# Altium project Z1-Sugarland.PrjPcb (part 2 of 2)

## Sheet Z1-Sugarland-Simplified.SchDoc
size 1219 x 914 mm
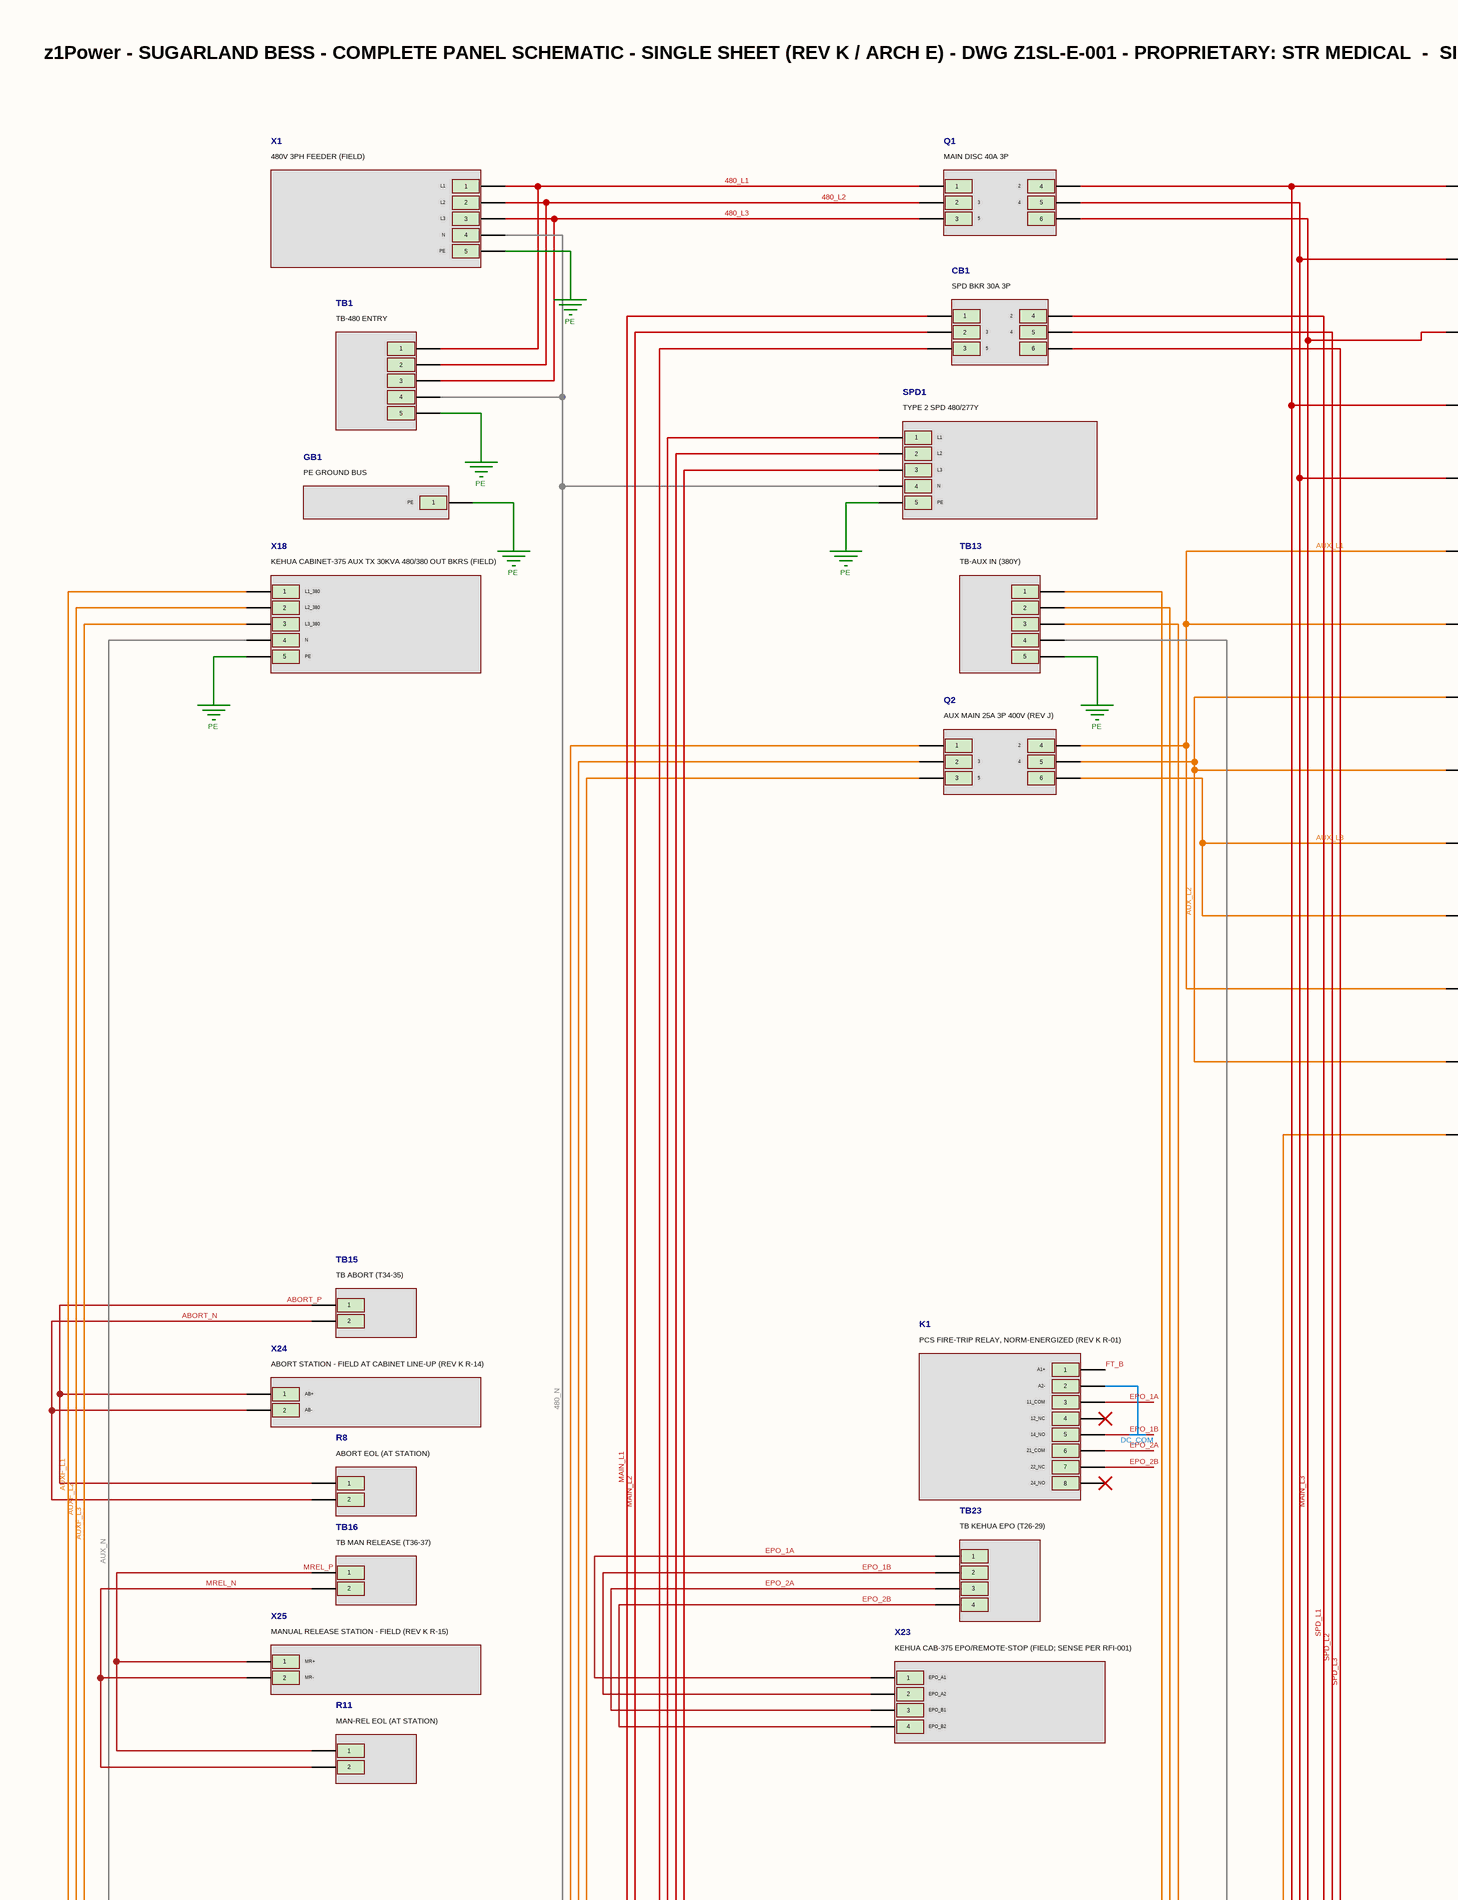
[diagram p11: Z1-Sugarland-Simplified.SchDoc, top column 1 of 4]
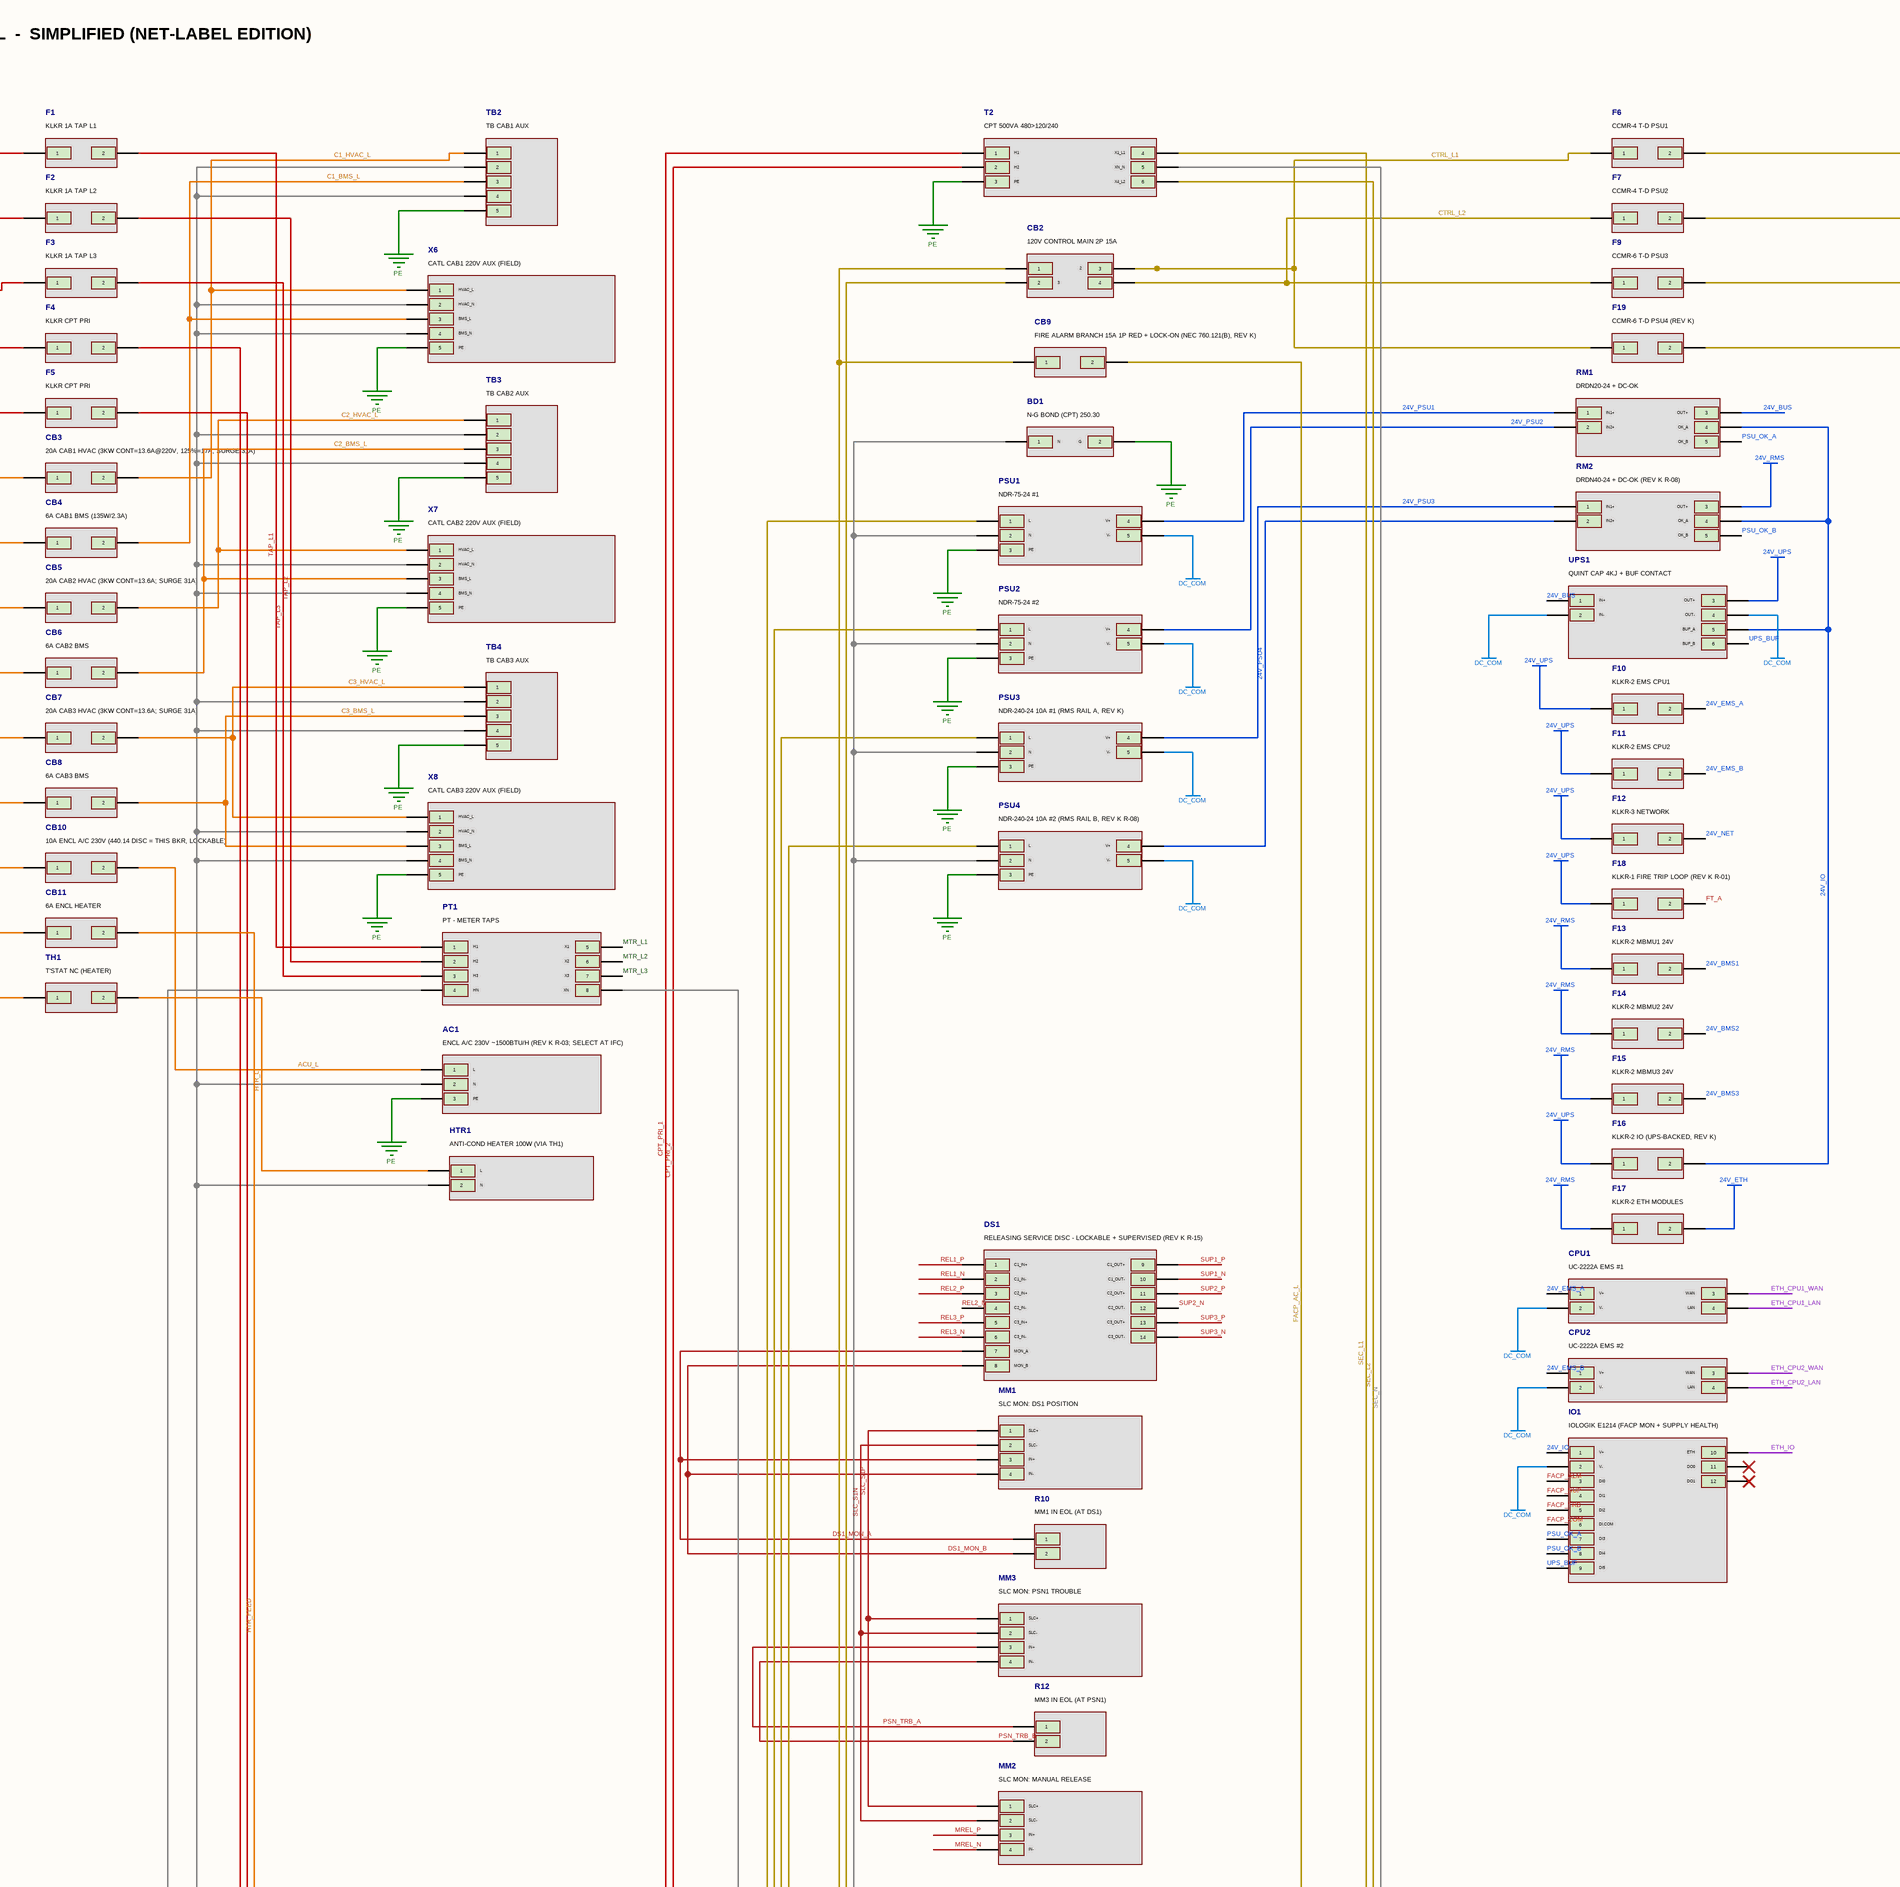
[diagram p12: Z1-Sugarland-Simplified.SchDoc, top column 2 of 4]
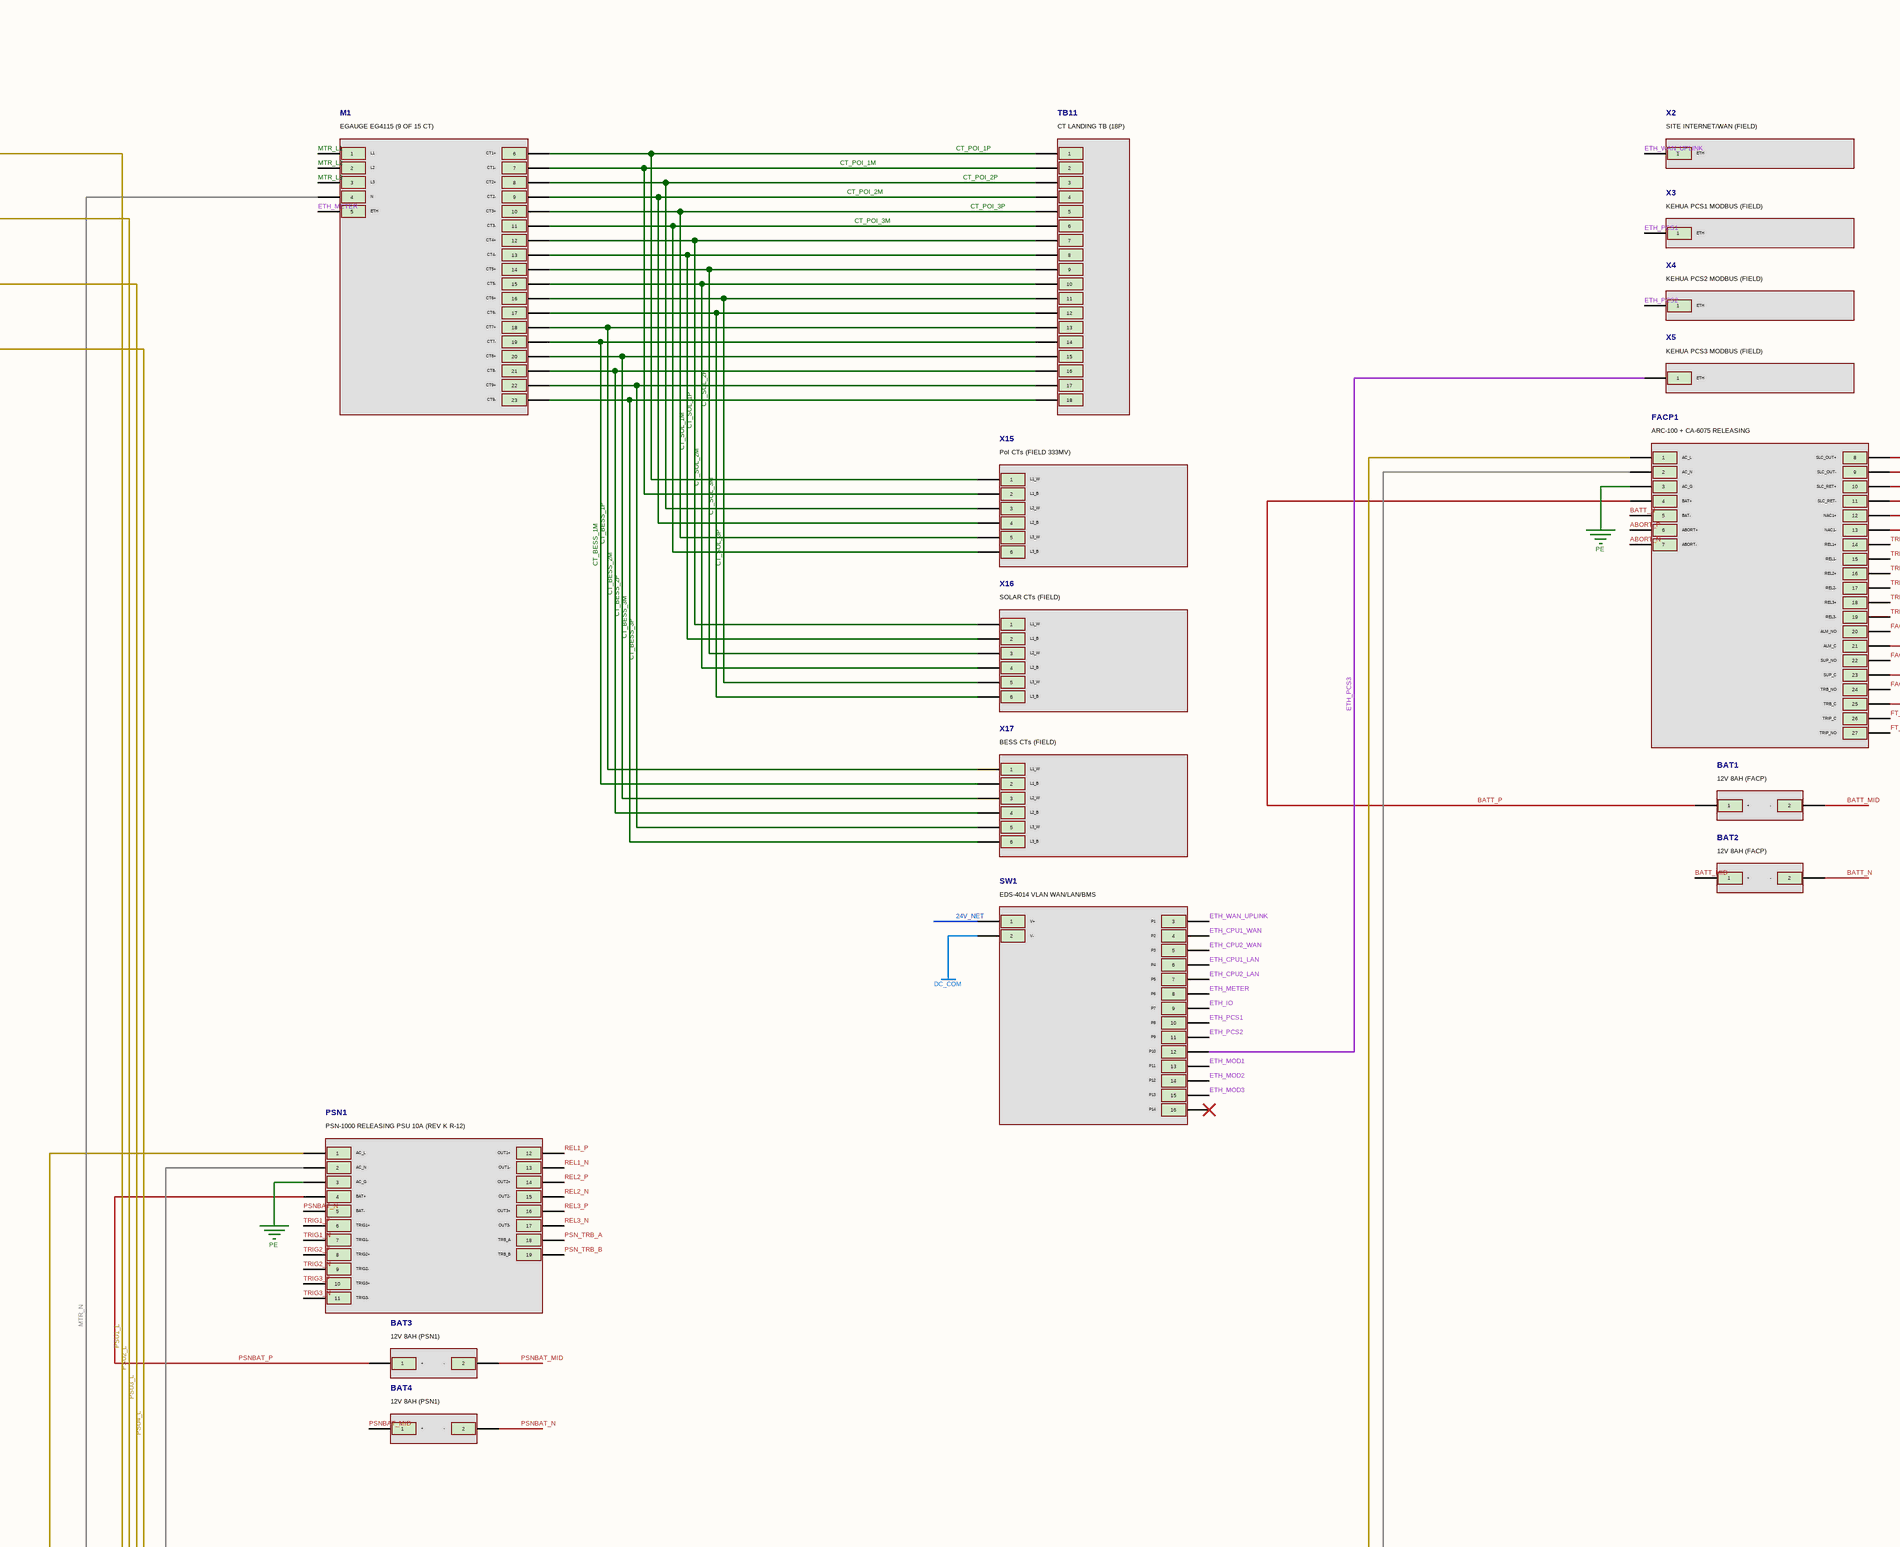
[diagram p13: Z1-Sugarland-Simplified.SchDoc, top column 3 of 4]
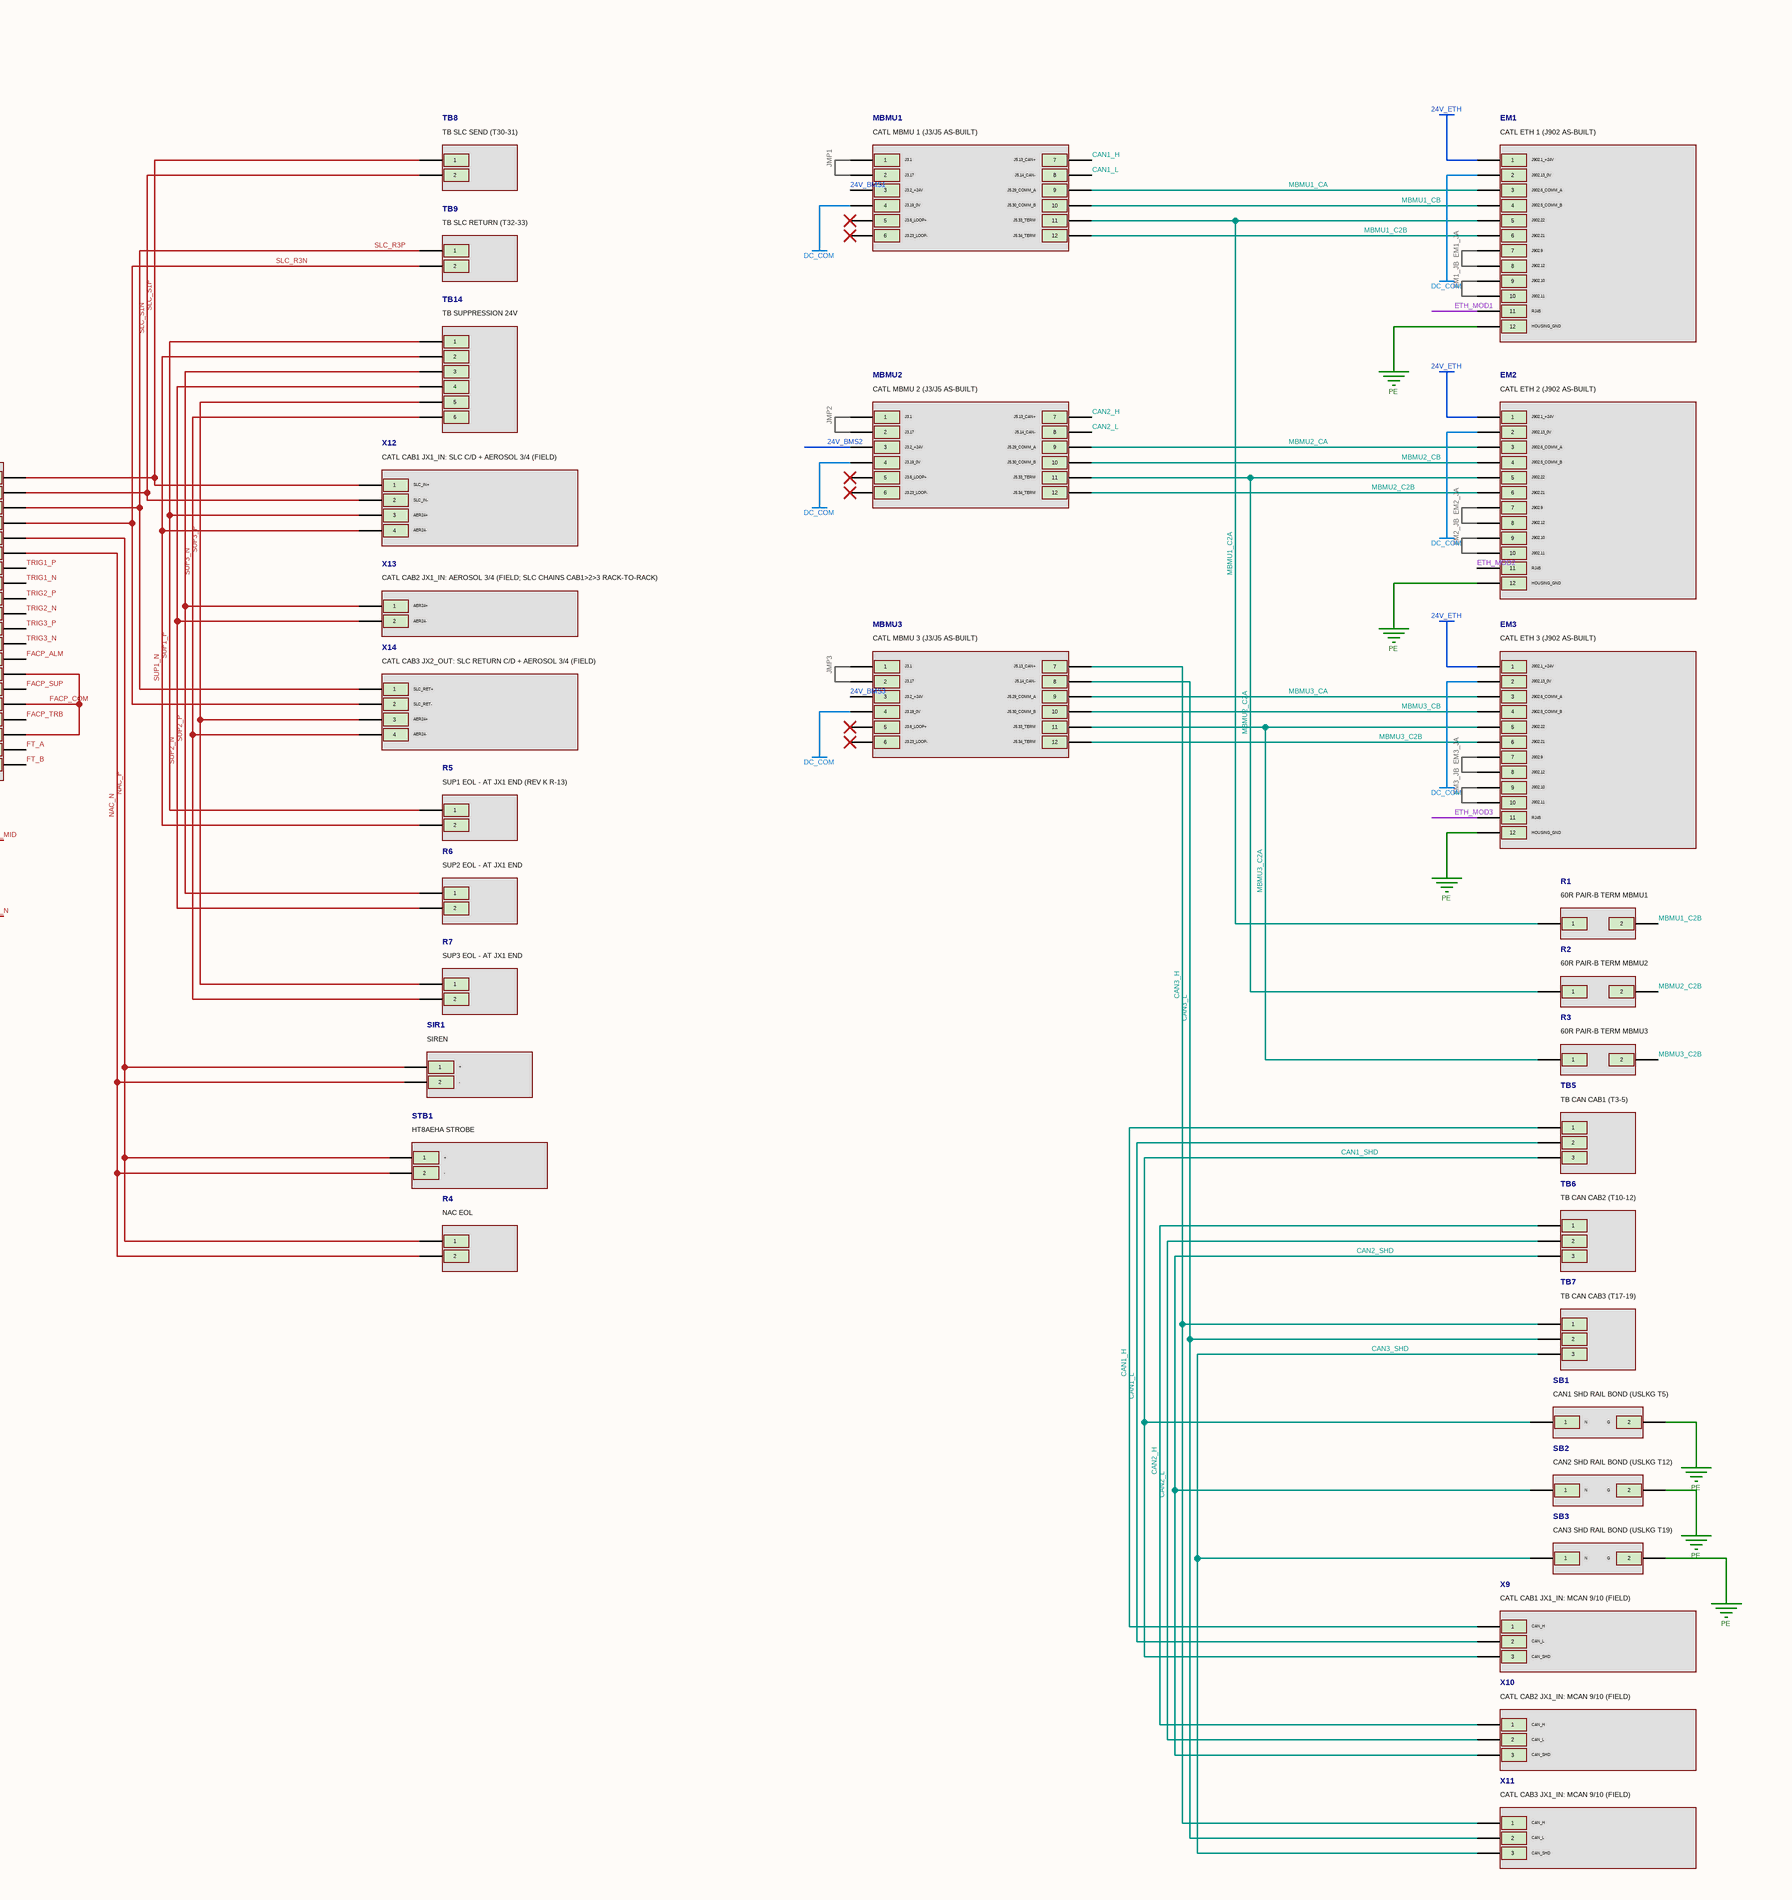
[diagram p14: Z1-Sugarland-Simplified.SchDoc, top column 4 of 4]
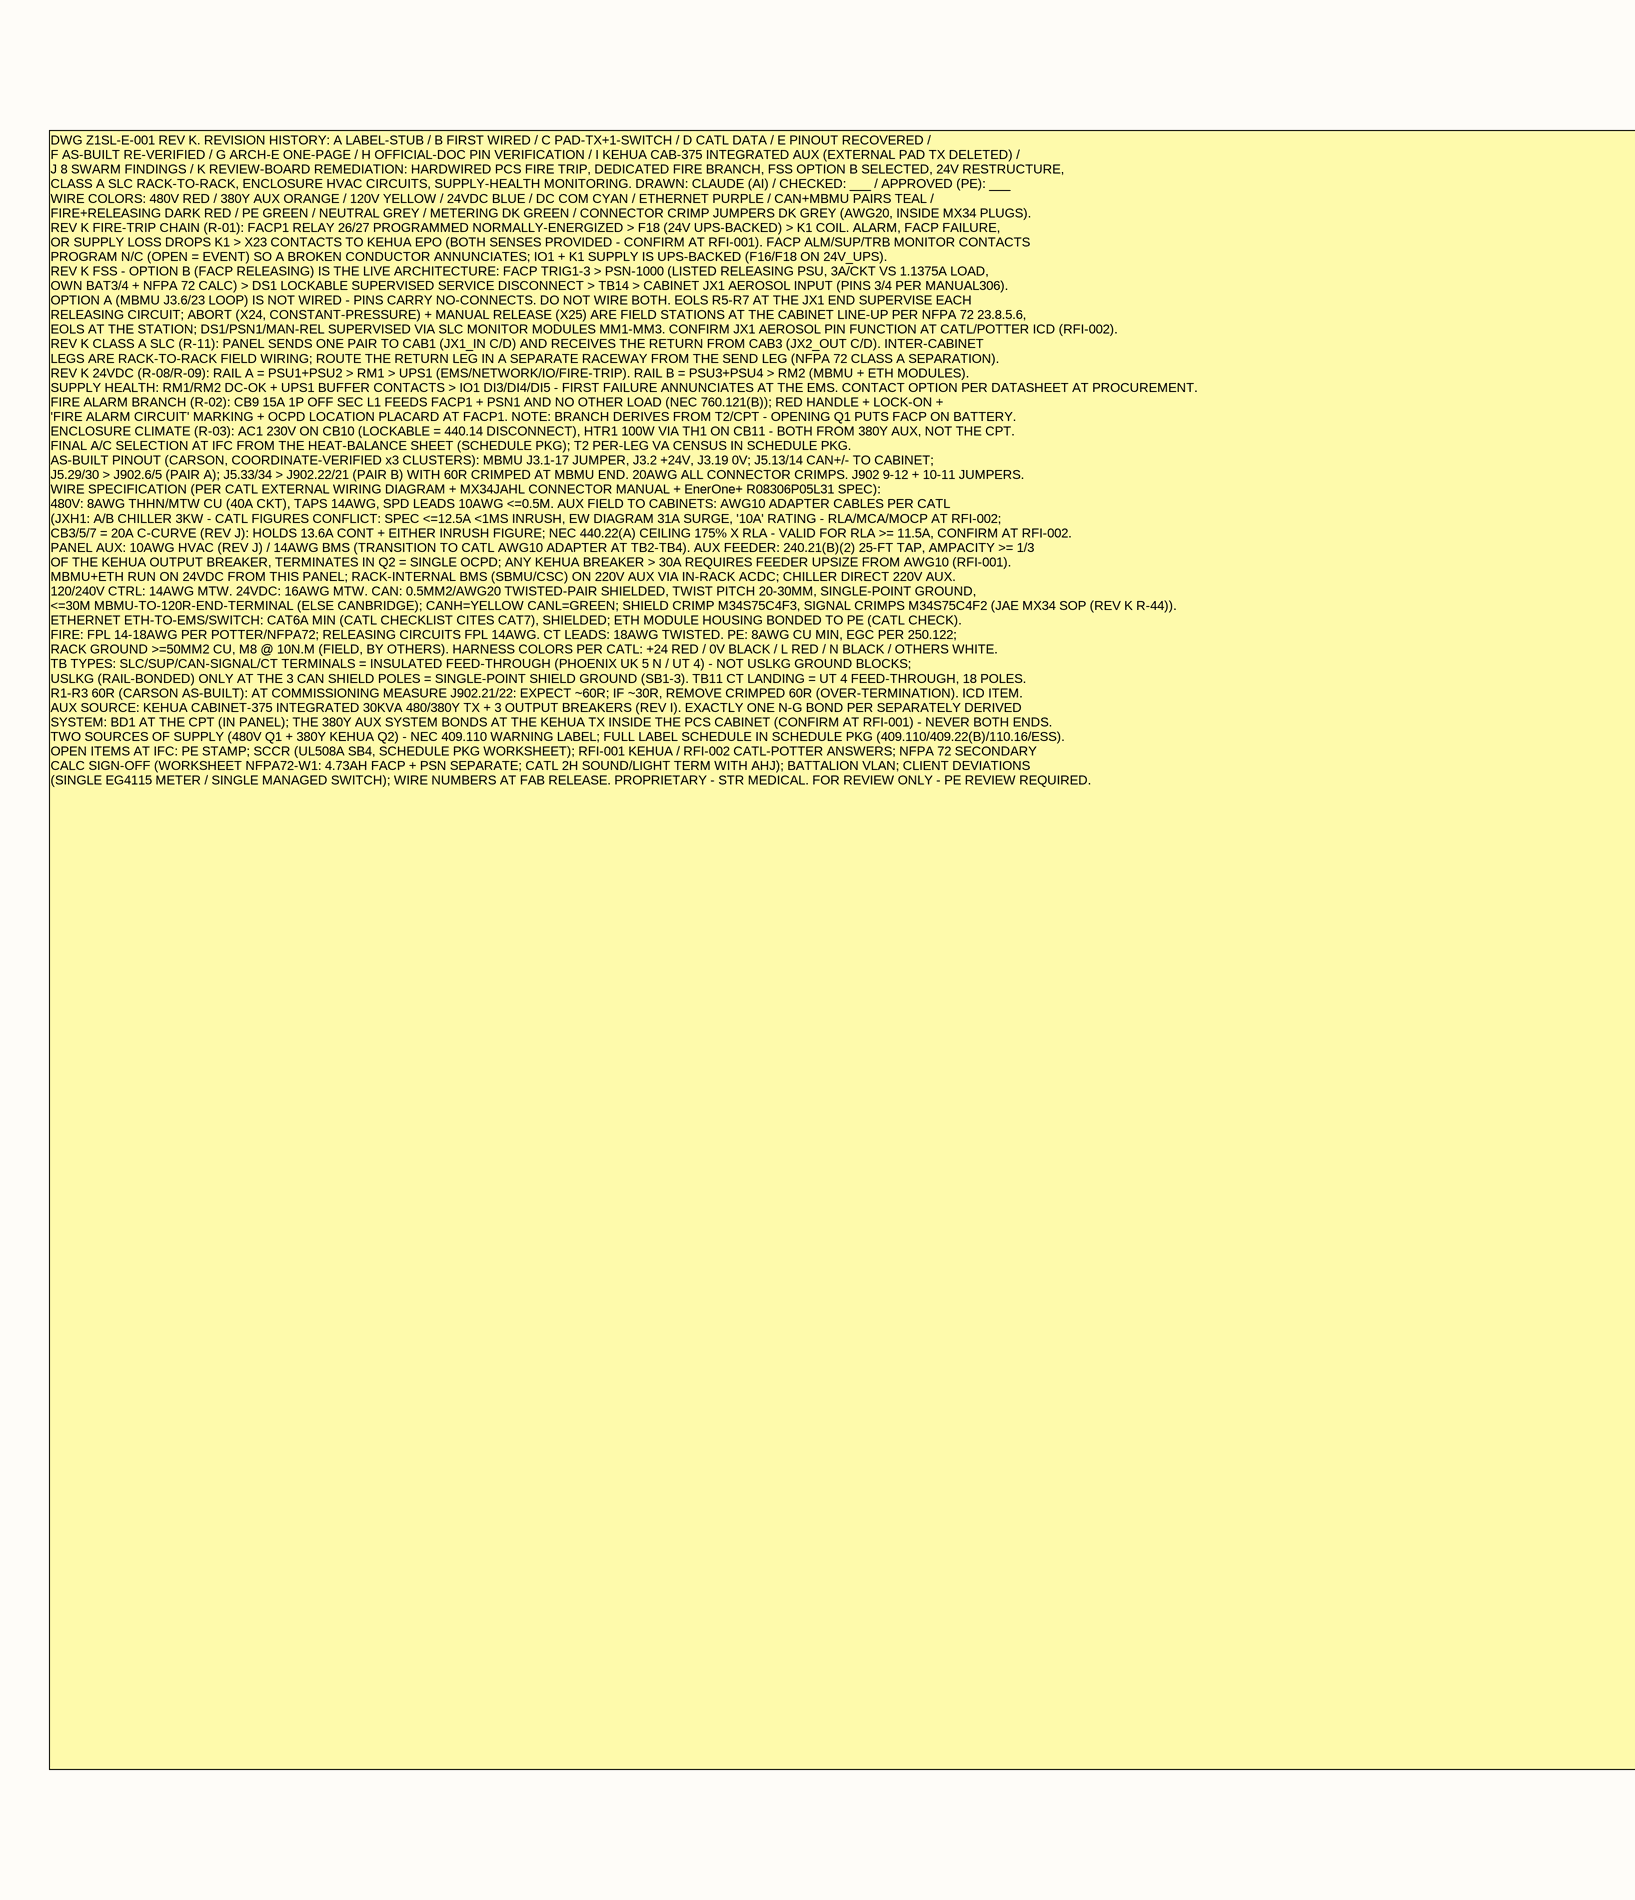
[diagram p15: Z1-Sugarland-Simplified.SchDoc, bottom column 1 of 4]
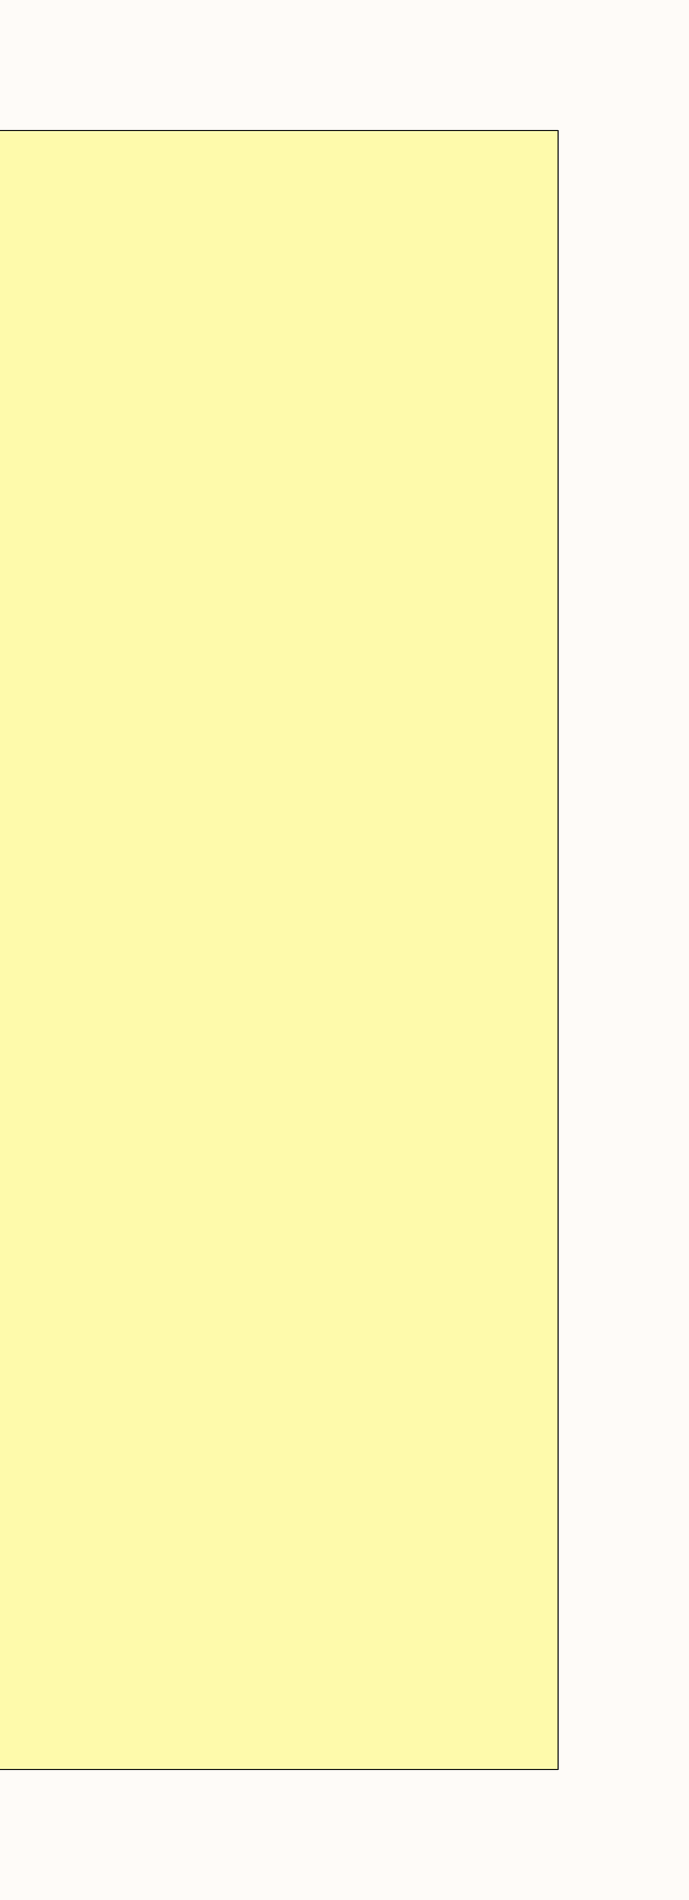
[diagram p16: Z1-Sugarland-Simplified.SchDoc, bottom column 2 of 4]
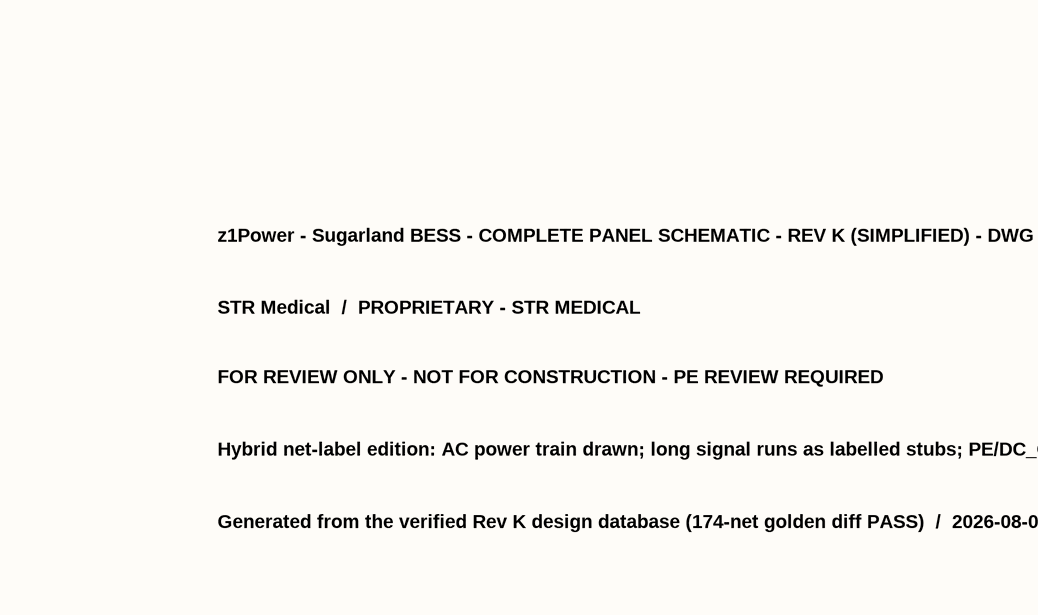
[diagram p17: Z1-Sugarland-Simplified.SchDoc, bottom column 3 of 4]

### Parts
(Parts that share a designator on the sheet are numbered #1, #2 ... from top to bottom, then left to right.)
AC1#2  ENCL A/C 230V ~1500BTU/H (REV K R-03; SELECT AT IFC)
BAT1#2  12V 8AH (FACP)
BAT2#2  12V 8AH (FACP)
BAT3#2  12V 8AH (PSN1)
BAT4#2  12V 8AH (PSN1)
BD1#2  N-G BOND (CPT) 250.30
CB1#2  SPD BKR 30A 3P
CB2#2  120V CONTROL MAIN 2P 15A
CB3#2  20A CAB1 HVAC (3KW CONT=13.6A@220V, 125%=17A; SURGE 31A)
CB4#2  6A CAB1 BMS (135W/2.3A)
CB5#2  20A CAB2 HVAC (3KW CONT=13.6A; SURGE 31A)
CB6#2  6A CAB2 BMS
CB7#2  20A CAB3 HVAC (3KW CONT=13.6A; SURGE 31A)
CB8#2  6A CAB3 BMS
CB9#2  FIRE ALARM BRANCH 15A 1P RED + LOCK-ON (NEC 760.121(B), REV K)
CB10#2  10A ENCL A/C 230V (440.14 DISC = THIS BKR, LOCKABLE)
CB11#2  6A ENCL HEATER
CPU1#2  UC-2222A EMS #1
CPU2#2  UC-2222A EMS #2
DS1#2  RELEASING SERVICE DISC - LOCKABLE + SUPERVISED (REV K R-15)
EM1#2  CATL ETH 1 (J902 AS-BUILT)
EM2#2  CATL ETH 2 (J902 AS-BUILT)
EM3#2  CATL ETH 3 (J902 AS-BUILT)
F1#2  KLKR 1A TAP L1
F2#2  KLKR 1A TAP L2
F3#2  KLKR 1A TAP L3
F4#2  KLKR CPT PRI
F5#2  KLKR CPT PRI
F6#2  CCMR-4 T-D PSU1
F7#2  CCMR-4 T-D PSU2
F9#2  CCMR-6 T-D PSU3
F10#2  KLKR-2 EMS CPU1
F11#2  KLKR-2 EMS CPU2
F12#2  KLKR-3 NETWORK
F13#2  KLKR-2 MBMU1 24V
F14#2  KLKR-2 MBMU2 24V
F15#2  KLKR-2 MBMU3 24V
F16#2  KLKR-2 IO (UPS-BACKED, REV K)
F17#2  KLKR-2 ETH MODULES
F18#2  KLKR-1 FIRE TRIP LOOP (REV K R-01)
F19#2  CCMR-6 T-D PSU4 (REV K)
FACP1#2  ARC-100 + CA-6075 RELEASING
GB1#2  PE GROUND BUS
HTR1#2  ANTI-COND HEATER 100W (VIA TH1)
IO1#2  IOLOGIK E1214 (FACP MON + SUPPLY HEALTH)
K1#2  PCS FIRE-TRIP RELAY, NORM-ENERGIZED (REV K R-01)
M1#2  EGAUGE EG4115 (9 OF 15 CT)
MBMU1#2  CATL MBMU 1 (J3/J5 AS-BUILT)
MBMU2#2  CATL MBMU 2 (J3/J5 AS-BUILT)
MBMU3#2  CATL MBMU 3 (J3/J5 AS-BUILT)
MM1#2  SLC MON: DS1 POSITION
MM2#2  SLC MON: MANUAL RELEASE
MM3#2  SLC MON: PSN1 TROUBLE
PSN1#2  PSN-1000 RELEASING PSU 10A (REV K R-12)
PSU1#2  NDR-75-24 #1
PSU2#2  NDR-75-24 #2
PSU3#2  NDR-240-24 10A #1 (RMS RAIL A, REV K)
PSU4#2  NDR-240-24 10A #2 (RMS RAIL B, REV K R-08)
PT1#2  PT - METER TAPS
Q1#2  MAIN DISC 40A 3P
Q2#2  AUX MAIN 25A 3P 400V (REV J)
R1#2  60R PAIR-B TERM MBMU1
R2#2  60R PAIR-B TERM MBMU2
R3#2  60R PAIR-B TERM MBMU3
R4#2  NAC EOL
R5#2  SUP1 EOL - AT JX1 END (REV K R-13)
R6#2  SUP2 EOL - AT JX1 END
R7#2  SUP3 EOL - AT JX1 END
R8#2  ABORT EOL (AT STATION)
R10#2  MM1 IN EOL (AT DS1)
R11#2  MAN-REL EOL (AT STATION)
R12#2  MM3 IN EOL (AT PSN1)
RM1#2  DRDN20-24 + DC-OK
RM2#2  DRDN40-24 + DC-OK (REV K R-08)
SB1#2  CAN1 SHD RAIL BOND (USLKG T5)
SB2#2  CAN2 SHD RAIL BOND (USLKG T12)
SB3#2  CAN3 SHD RAIL BOND (USLKG T19)
SIR1#2  SIREN
SPD1#2  TYPE 2 SPD 480/277Y
STB1#2  HT8AEHA STROBE
SW1#2  EDS-4014 VLAN WAN/LAN/BMS
T2#2  CPT 500VA 480>120/240
TB1#2  TB-480 ENTRY
TB2#2  TB CAB1 AUX
TB3#2  TB CAB2 AUX
TB4#2  TB CAB3 AUX
TB5#2  TB CAN CAB1 (T3-5)
TB6#2  TB CAN CAB2 (T10-12)
TB7#2  TB CAN CAB3 (T17-19)
TB8#2  TB SLC SEND (T30-31)
TB9#2  TB SLC RETURN (T32-33)
TB11#2  CT LANDING TB (18P)
TB13#2  TB-AUX IN (380Y)
TB14#2  TB SUPPRESSION 24V
TB15#2  TB ABORT (T34-35)
TB16#2  TB MAN RELEASE (T36-37)
TB23#2  TB KEHUA EPO (T26-29)
TH1#2  T'STAT NC (HEATER)
UPS1#2  QUINT CAP 4KJ + BUF CONTACT
X1#2  480V 3PH FEEDER (FIELD)
X2#2  SITE INTERNET/WAN (FIELD)
X3#2  KEHUA PCS1 MODBUS (FIELD)
X4#2  KEHUA PCS2 MODBUS (FIELD)
X5#2  KEHUA PCS3 MODBUS (FIELD)
X6#2  CATL CAB1 220V AUX (FIELD)
X7#2  CATL CAB2 220V AUX (FIELD)
X8#2  CATL CAB3 220V AUX (FIELD)
X9#2  CATL CAB1 JX1_IN: MCAN 9/10 (FIELD)
X10#2  CATL CAB2 JX1_IN: MCAN 9/10 (FIELD)
X11#2  CATL CAB3 JX1_IN: MCAN 9/10 (FIELD)
X12#2  CATL CAB1 JX1_IN: SLC C/D + AEROSOL 3/4 (FIELD)
X13#2  CATL CAB2 JX1_IN: AEROSOL 3/4 (FIELD; SLC CHAINS CAB1>2>3 RACK-TO-RACK)
X14#2  CATL CAB3 JX2_OUT: SLC RETURN C/D + AEROSOL 3/4 (FIELD)
X15#2  PoI CTs (FIELD 333MV)
X16#2  SOLAR CTs (FIELD)
X17#2  BESS CTs (FIELD)
X18#2  KEHUA CABINET-375 AUX TX 30KVA 480/380 OUT BKRS (FIELD)
X23#2  KEHUA CAB-375 EPO/REMOTE-STOP (FIELD; SENSE PER RFI-001)
X24#2  ABORT STATION - FIELD AT CABINET LINE-UP (REV K R-14)
X25#2  MANUAL RELEASE STATION - FIELD (REV K R-15)

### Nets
24V_ETH: EM1#2.1(J902.1_+24V) EM2#2.1(J902.1_+24V) EM3#2.1(J902.1_+24V) F17#2.2
24V_RMS: F13#2.1 F14#2.1 F15#2.1 F17#2.1 RM2#2.3(OUT+)
24V_UPS: F10#2.1 F11#2.1 F12#2.1 F16#2.1 F18#2.1 UPS1#2.3(OUT+)
DC_COM: CPU1#2.2(V-) CPU2#2.2(V-) EM1#2.2(J902.13_0V) EM2#2.2(J902.13_0V) EM3#2.2(J902.13_0V) IO1#2.2(V-) K1#2.2(A2-) MBMU1#2.4(J3.19_0V) MBMU2#2.4(J3.19_0V) MBMU3#2.4(J3.19_0V) PSU1#2.5(V-) PSU2#2.5(V-) PSU3#2.5(V-) PSU4#2.5(V-) SW1#2.2(V-) UPS1#2.2(IN-) UPS1#2.4(OUT-)
PE: AC1#2.3(PE) BD1#2.2(G) EM1#2.12(HOUSING_GND) EM2#2.12(HOUSING_GND) EM3#2.12(HOUSING_GND) FACP1#2.3(AC_G) GB1#2.1(PE) PSN1#2.3(AC_G) PSU1#2.3(PE) PSU2#2.3(PE) PSU3#2.3(PE) PSU4#2.3(PE) SB1#2.2(G) SB2#2.2(G) SB3#2.2(G) SPD1#2.5(PE) T2#2.3(PE) TB1#2.5 TB2#2.5 TB3#2.5 TB4#2.5 TB13#2.5 X1#2.5(PE) X6#2.5(PE) X7#2.5(PE) X8#2.5(PE) X18#2.5(PE)
24V_BMS1: F13#2.2 MBMU1#2.3(J3.2_+24V)
24V_BMS2: F14#2.2 MBMU2#2.3(J3.2_+24V)
24V_BMS3: F15#2.2 MBMU3#2.3(J3.2_+24V)
24V_BUS: RM1#2.3(OUT+) UPS1#2.1(IN+)
24V_EMS_A: CPU1#2.1(V+) F10#2.2
24V_EMS_B: CPU2#2.1(V+) F11#2.2
24V_IO: F16#2.2 IO1#2.1(V+) RM1#2.4(OK_A) RM2#2.4(OK_A) UPS1#2.5(BUF_A)
24V_NET: F12#2.2 SW1#2.1(V+)
24V_PSU1: PSU1#2.4(V+) RM1#2.1(IN1+)
24V_PSU2: PSU2#2.4(V+) RM1#2.2(IN2+)
24V_PSU3: PSU3#2.4(V+) RM2#2.1(IN1+)
24V_PSU4: PSU4#2.4(V+) RM2#2.2(IN2+)
480_L1: Q1#2.1 TB1#2.1 X1#2.1(L1)
480_L2: Q1#2.2 TB1#2.2 X1#2.2(L2)
480_L3: Q1#2.3 TB1#2.3 X1#2.3(L3)
480_N: PT1#2.4(HN) SPD1#2.4(N) TB1#2.4 X1#2.4(N)
ABORT_N: FACP1#2.7(ABORT-) R8#2.2 TB15#2.2 X24#2.2(AB-)
ABORT_P: FACP1#2.6(ABORT+) R8#2.1 TB15#2.1 X24#2.1(AB+)
ACU_L: AC1#2.1(L) CB10#2.2
AUX_L1: CB3#2.1 CB4#2.1 CB10#2.1 Q2#2.4
AUX_L2: CB5#2.1 CB6#2.1 CB11#2.1 Q2#2.5
AUX_L3: CB7#2.1 CB8#2.1 Q2#2.6
AUX_N: AC1#2.2(N) HTR1#2.2(N) TB2#2.2 TB2#2.4 TB3#2.2 TB3#2.4 TB4#2.2 TB4#2.4 TB13#2.4 X6#2.2(HVAC_N) X6#2.4(BMS_N) X7#2.2(HVAC_N) X7#2.4(BMS_N) X8#2.2(HVAC_N) X8#2.4(BMS_N) X18#2.4(N)
AUXF_L1: Q2#2.1 TB13#2.1 X18#2.1(L1_380)
AUXF_L2: Q2#2.2 TB13#2.2 X18#2.2(L2_380)
AUXF_L3: Q2#2.3 TB13#2.3 X18#2.3(L3_380)
BATT_MID: BAT1#2.2(-) BAT2#2.1(+)
BATT_N: BAT2#2.2(-) FACP1#2.5(BAT-)
BATT_P: BAT1#2.1(+) FACP1#2.4(BAT+)
C1_BMS_L: CB4#2.2 TB2#2.3 X6#2.3(BMS_L)
C1_HVAC_L: CB3#2.2 TB2#2.1 X6#2.1(HVAC_L)
C2_BMS_L: CB6#2.2 TB3#2.3 X7#2.3(BMS_L)
C2_HVAC_L: CB5#2.2 TB3#2.1 X7#2.1(HVAC_L)
C3_BMS_L: CB8#2.2 TB4#2.3 X8#2.3(BMS_L)
C3_HVAC_L: CB7#2.2 TB4#2.1 X8#2.1(HVAC_L)
CAN1_H: MBMU1#2.7(J5.13_CAN+) TB5#2.1 X9#2.1(CAN_H)
CAN1_L: MBMU1#2.8(J5.14_CAN-) TB5#2.2 X9#2.2(CAN_L)
CAN1_SHD: SB1#2.1(N) TB5#2.3 X9#2.3(CAN_SHD)
CAN2_H: MBMU2#2.7(J5.13_CAN+) TB6#2.1 X10#2.1(CAN_H)
CAN2_L: MBMU2#2.8(J5.14_CAN-) TB6#2.2 X10#2.2(CAN_L)
CAN2_SHD: SB2#2.1(N) TB6#2.3 X10#2.3(CAN_SHD)
CAN3_H: MBMU3#2.7(J5.13_CAN+) TB7#2.1 X11#2.1(CAN_H)
CAN3_L: MBMU3#2.8(J5.14_CAN-) TB7#2.2 X11#2.2(CAN_L)
CAN3_SHD: SB3#2.1(N) TB7#2.3 X11#2.3(CAN_SHD)
CPT_PRI_1: F4#2.2 T2#2.1(H1)
CPT_PRI_2: F5#2.2 T2#2.2(H2)
CT_BESS_1M: M1#2.19(CT7-) TB11#2.14 X17#2.2(L1_B)
CT_BESS_1P: M1#2.18(CT7+) TB11#2.13 X17#2.1(L1_W)
CT_BESS_2M: M1#2.21(CT8-) TB11#2.16 X17#2.4(L2_B)
CT_BESS_2P: M1#2.20(CT8+) TB11#2.15 X17#2.3(L2_W)
CT_BESS_3M: M1#2.23(CT9-) TB11#2.18 X17#2.6(L3_B)
CT_BESS_3P: M1#2.22(CT9+) TB11#2.17 X17#2.5(L3_W)
CT_POI_1M: M1#2.7(CT1-) TB11#2.2 X15#2.2(L1_B)
CT_POI_1P: M1#2.6(CT1+) TB11#2.1 X15#2.1(L1_W)
CT_POI_2M: M1#2.9(CT2-) TB11#2.4 X15#2.4(L2_B)
CT_POI_2P: M1#2.8(CT2+) TB11#2.3 X15#2.3(L2_W)
CT_POI_3M: M1#2.11(CT3-) TB11#2.6 X15#2.6(L3_B)
CT_POI_3P: M1#2.10(CT3+) TB11#2.5 X15#2.5(L3_W)
CT_SOL_1M: M1#2.13(CT4-) TB11#2.8 X16#2.2(L1_B)
CT_SOL_1P: M1#2.12(CT4+) TB11#2.7 X16#2.1(L1_W)
CT_SOL_2M: M1#2.15(CT5-) TB11#2.10 X16#2.4(L2_B)
CT_SOL_2P: M1#2.14(CT5+) TB11#2.9 X16#2.3(L2_W)
CT_SOL_3M: M1#2.17(CT6-) TB11#2.12 X16#2.6(L3_B)
CT_SOL_3P: M1#2.16(CT6+) TB11#2.11 X16#2.5(L3_W)
CTRL_L1: CB2#2.3 F6#2.1 F19#2.1
CTRL_L2: CB2#2.4 F7#2.1 F9#2.1
DS1_MON_A: DS1#2.7(MON_A) MM1#2.3(IN+) R10#2.1
DS1_MON_B: DS1#2.8(MON_B) MM1#2.4(IN-) R10#2.2
EM1_JA: EM1#2.7(J902.9) EM1#2.8(J902.12)
EM1_JB: EM1#2.9(J902.10) EM1#2.10(J902.11)
EM2_JA: EM2#2.7(J902.9) EM2#2.8(J902.12)
EM2_JB: EM2#2.9(J902.10) EM2#2.10(J902.11)
EM3_JA: EM3#2.7(J902.9) EM3#2.8(J902.12)
EM3_JB: EM3#2.9(J902.10) EM3#2.10(J902.11)
EPO_1A: K1#2.3(11_COM) TB23#2.1 X23#2.1(EPO_A1)
EPO_1B: K1#2.5(14_NO) TB23#2.2 X23#2.2(EPO_A2)
EPO_2A: K1#2.6(21_COM) TB23#2.3 X23#2.3(EPO_B1)
EPO_2B: K1#2.7(22_NC) TB23#2.4 X23#2.4(EPO_B2)
ETH_CPU1_LAN: CPU1#2.4(LAN) SW1#2.6(P4)
ETH_CPU1_WAN: CPU1#2.3(WAN) SW1#2.4(P2)
ETH_CPU2_LAN: CPU2#2.4(LAN) SW1#2.7(P5)
ETH_CPU2_WAN: CPU2#2.3(WAN) SW1#2.5(P3)
ETH_IO: IO1#2.10(ETH) SW1#2.9(P7)
ETH_METER: M1#2.5(ETH) SW1#2.8(P6)
ETH_MOD1: EM1#2.11(RJ45) SW1#2.13(P11)
ETH_MOD2: EM2#2.11(RJ45) SW1#2.14(P12)
ETH_MOD3: EM3#2.11(RJ45) SW1#2.15(P13)
ETH_PCS1: SW1#2.10(P8) X3#2.1(ETH)
ETH_PCS2: SW1#2.11(P9) X4#2.1(ETH)
ETH_PCS3: SW1#2.12(P10) X5#2.1(ETH)
ETH_WAN_UPLINK: SW1#2.3(P1) X2#2.1(ETH)
FACP_AC_L: CB9#2.2 FACP1#2.1(AC_L) PSN1#2.1(AC_L)
FACP_ALM: FACP1#2.20(ALM_NO) IO1#2.3(DI0)
FACP_COM: FACP1#2.21(ALM_C) FACP1#2.23(SUP_C) FACP1#2.25(TRB_C) IO1#2.6(DI.COM)
FACP_SUP: FACP1#2.22(SUP_NO) IO1#2.4(DI1)
FACP_TRB: FACP1#2.24(TRB_NO) IO1#2.5(DI2)
FT_A: F18#2.2 FACP1#2.26(TRIP_C)
FT_B: FACP1#2.27(TRIP_NO) K1#2.1(A1+)
HTR_FEED: CB11#2.2 TH1#2.1
HTR_L: HTR1#2.1(L) TH1#2.2
JMP1: MBMU1#2.1(J3.1) MBMU1#2.2(J3.17)
JMP2: MBMU2#2.1(J3.1) MBMU2#2.2(J3.17)
JMP3: MBMU3#2.1(J3.1) MBMU3#2.2(J3.17)
MAIN_L1: CB1#2.1 F1#2.1 F4#2.1 Q1#2.4
MAIN_L2: CB1#2.2 F2#2.1 F5#2.1 Q1#2.5
MAIN_L3: CB1#2.3 F3#2.1 Q1#2.6
MBMU1_C2A: EM1#2.5(J902.22) MBMU1#2.11(J5.33_TERM) R1#2.1
MBMU1_C2B: EM1#2.6(J902.21) MBMU1#2.12(J5.34_TERM) R1#2.2
MBMU1_CA: EM1#2.3(J902.6_COMM_A) MBMU1#2.9(J5.29_COMM_A)
MBMU1_CB: EM1#2.4(J902.5_COMM_B) MBMU1#2.10(J5.30_COMM_B)
MBMU2_C2A: EM2#2.5(J902.22) MBMU2#2.11(J5.33_TERM) R2#2.1
MBMU2_C2B: EM2#2.6(J902.21) MBMU2#2.12(J5.34_TERM) R2#2.2
MBMU2_CA: EM2#2.3(J902.6_COMM_A) MBMU2#2.9(J5.29_COMM_A)
MBMU2_CB: EM2#2.4(J902.5_COMM_B) MBMU2#2.10(J5.30_COMM_B)
MBMU3_C2A: EM3#2.5(J902.22) MBMU3#2.11(J5.33_TERM) R3#2.1
MBMU3_C2B: EM3#2.6(J902.21) MBMU3#2.12(J5.34_TERM) R3#2.2
MBMU3_CA: EM3#2.3(J902.6_COMM_A) MBMU3#2.9(J5.29_COMM_A)
MBMU3_CB: EM3#2.4(J902.5_COMM_B) MBMU3#2.10(J5.30_COMM_B)
MREL_N: MM2#2.4(IN-) R11#2.2 TB16#2.2 X25#2.2(MR-)
MREL_P: MM2#2.3(IN+) R11#2.1 TB16#2.1 X25#2.1(MR+)
MTR_L1: M1#2.1(L1) PT1#2.5(X1)
MTR_L2: M1#2.2(L2) PT1#2.6(X2)
MTR_L3: M1#2.3(L3) PT1#2.7(X3)
MTR_N: M1#2.4(N) PT1#2.8(XN)
NAC_N: FACP1#2.13(NAC1-) R4#2.2 SIR1#2.2(-) STB1#2.2(-)
NAC_P: FACP1#2.12(NAC1+) R4#2.1 SIR1#2.1(+) STB1#2.1(+)
PSN_TRB_A: MM3#2.3(IN+) PSN1#2.18(TRB_A) R12#2.1
PSN_TRB_B: MM3#2.4(IN-) PSN1#2.19(TRB_B) R12#2.2
PSNBAT_MID: BAT3#2.2(-) BAT4#2.1(+)
PSNBAT_N: BAT4#2.2(-) PSN1#2.5(BAT-)
PSNBAT_P: BAT3#2.1(+) PSN1#2.4(BAT+)
PSU1_L: F6#2.2 PSU1#2.1(L)
PSU2_L: F7#2.2 PSU2#2.1(L)
PSU3_L: F9#2.2 PSU3#2.1(L)
PSU4_L: F19#2.2 PSU4#2.1(L)
PSU_OK_A: IO1#2.7(DI3) RM1#2.5(OK_B)
PSU_OK_B: IO1#2.8(DI4) RM2#2.5(OK_B)
REL1_N: DS1#2.2(C1_IN-) PSN1#2.13(OUT1-)
REL1_P: DS1#2.1(C1_IN+) PSN1#2.12(OUT1+)
REL2_N: DS1#2.4(C2_IN-) PSN1#2.15(OUT2-)
REL2_P: DS1#2.3(C2_IN+) PSN1#2.14(OUT2+)
REL3_N: DS1#2.6(C3_IN-) PSN1#2.17(OUT3-)
REL3_P: DS1#2.5(C3_IN+) PSN1#2.16(OUT3+)
SEC_L1: CB2#2.1 CB9#2.1 T2#2.4(X1_L1)
SEC_L2: CB2#2.2 T2#2.6(X4_L2)
SEC_N: BD1#2.1(N) FACP1#2.2(AC_N) PSN1#2.2(AC_N) PSU1#2.2(N) PSU2#2.2(N) PSU3#2.2(N) PSU4#2.2(N) T2#2.5(XN_N)
SLC_R3N: FACP1#2.11(SLC_RET-) TB9#2.2 X14#2.2(SLC_RET-)
SLC_R3P: FACP1#2.10(SLC_RET+) TB9#2.1 X14#2.1(SLC_RET+)
SLC_S1N: FACP1#2.9(SLC_OUT-) MM1#2.2(SLC-) MM2#2.2(SLC-) MM3#2.2(SLC-) TB8#2.2 X12#2.2(SLC_IN-)
SLC_S1P: FACP1#2.8(SLC_OUT+) MM1#2.1(SLC+) MM2#2.1(SLC+) MM3#2.1(SLC+) TB8#2.1 X12#2.1(SLC_IN+)
SPD_L1: CB1#2.4 SPD1#2.1(L1)
SPD_L2: CB1#2.5 SPD1#2.2(L2)
SPD_L3: CB1#2.6 SPD1#2.3(L3)
SUP1_N: DS1#2.10(C1_OUT-) R5#2.2 TB14#2.2 X12#2.4(AER24-)
SUP1_P: DS1#2.9(C1_OUT+) R5#2.1 TB14#2.1 X12#2.3(AER24+)
SUP2_N: DS1#2.12(C2_OUT-) R6#2.2 TB14#2.4 X13#2.2(AER24-)
SUP2_P: DS1#2.11(C2_OUT+) R6#2.1 TB14#2.3 X13#2.1(AER24+)
SUP3_N: DS1#2.14(C3_OUT-) R7#2.2 TB14#2.6 X14#2.4(AER24-)
SUP3_P: DS1#2.13(C3_OUT+) R7#2.1 TB14#2.5 X14#2.3(AER24+)
TAP_L1: F1#2.2 PT1#2.1(H1)
TAP_L2: F2#2.2 PT1#2.2(H2)
TAP_L3: F3#2.2 PT1#2.3(H3)
TRIG1_N: FACP1#2.15(REL1-) PSN1#2.7(TRIG1-)
TRIG1_P: FACP1#2.14(REL1+) PSN1#2.6(TRIG1+)
TRIG2_N: FACP1#2.17(REL2-) PSN1#2.9(TRIG2-)
TRIG2_P: FACP1#2.16(REL2+) PSN1#2.8(TRIG2+)
TRIG3_N: FACP1#2.19(REL3-) PSN1#2.11(TRIG3-)
TRIG3_P: FACP1#2.18(REL3+) PSN1#2.10(TRIG3+)
UPS_BUF: IO1#2.9(DI5) UPS1#2.6(BUF_B)

Not connected (* = marked no-connect by the designer): IO1#2 11(DO0)* 12(DO1)*; K1#2 4(12_NC)* 8(24_NO)*; MBMU1#2 5(J3.6_LOOP+)* 6(J3.23_LOOP-)*; MBMU2#2 5(J3.6_LOOP+)* 6(J3.23_LOOP-)*; MBMU3#2 5(J3.6_LOOP+)* 6(J3.23_LOOP-)*; SW1#2 16(P14)*

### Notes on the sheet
- z1Power - SUGARLAND BESS - COMPLETE PANEL SCHEMATIC - SINGLE SHEET (REV K / ARCH E) - DWG Z1SL-E-001 - PROPRIETARY: STR MEDICAL  -  SIMPLIFIED (NET-LABEL EDITION)
- DWG Z1SL-E-001 REV K. REVISION HISTORY: A LABEL-STUB / B FIRST WIRED / C PAD-TX+1-SWITCH / D CATL DATA / E PINOUT RECOVERED /
  F AS-BUILT RE-VERIFIED / G ARCH-E ONE-PAGE / H OFFICIAL-DOC PIN VERIFICATION / I KEHUA CAB-375 INTEGRATED AUX (EXTERNAL PAD TX DELETED) /
  J 8 SWARM FINDINGS / K REVIEW-BOARD REMEDIATION: HARDWIRED PCS FIRE TRIP, DEDICATED FIRE BRANCH, FSS OPTION B SELECTED, 24V RESTRUCTURE,
  CLASS A SLC RACK-TO-RACK, ENCLOSURE HVAC CIRCUITS, SUPPLY-HEALTH MONITORING. DRAWN: CLAUDE (AI) / CHECKED: ___ / APPROVED (PE): ___
  WIRE COLORS: 480V RED / 380Y AUX ORANGE / 120V YELLOW / 24VDC BLUE / DC COM CYAN / ETHERNET PURPLE / CAN+MBMU PAIRS TEAL /
  FIRE+RELEASING DARK RED / PE GREEN / NEUTRAL GREY / METERING DK GREEN / CONNECTOR CRIMP JUMPERS DK GREY (AWG20, INSIDE MX34 PLUGS).
  REV K FIRE-TRIP CHAIN (R-01): FACP1 RELAY 26/27 PROGRAMMED NORMALLY-ENERGIZED > F18 (24V UPS-BACKED) > K1 COIL. ALARM, FACP FAILURE,
  OR SUPPLY LOSS DROPS K1 > X23 CONTACTS TO KEHUA EPO (BOTH SENSES PROVIDED - CONFIRM AT RFI-001). FACP ALM/SUP/TRB MONITOR CONTACTS
  PROGRAM N/C (OPEN = EVENT) SO A BROKEN CONDUCTOR ANNUNCIATES; IO1 + K1 SUPPLY IS UPS-BACKED (F16/F18 ON 24V_UPS).
  REV K FSS - OPTION B (FACP RELEASING) IS THE LIVE ARCHITECTURE: FACP TRIG1-3 > PSN-1000 (LISTED RELEASING PSU, 3A/CKT VS 1.1375A LOAD,
  OWN BAT3/4 + NFPA 72 CALC) > DS1 LOCKABLE SUPERVISED SERVICE DISCONNECT > TB14 > CABINET JX1 AEROSOL INPUT (PINS 3/4 PER MANUAL306).
  OPTION A (MBMU J3.6/23 LOOP) IS NOT WIRED - PINS CARRY NO-CONNECTS. DO NOT WIRE BOTH. EOLS R5-R7 AT THE JX1 END SUPERVISE EACH
  RELEASING CIRCUIT; ABORT (X24, CONSTANT-PRESSURE) + MANUAL RELEASE (X25) ARE FIELD STATIONS AT THE CABINET LINE-UP PER NFPA 72 23.8.5.6,
  EOLS AT THE STATION; DS1/PSN1/MAN-REL SUPERVISED VIA SLC MONITOR MODULES MM1-MM3. CONFIRM JX1 AEROSOL PIN FUNCTION AT CATL/POTTER ICD (RFI-002).
  REV K CLASS A SLC (R-11): PANEL SENDS ONE PAIR TO CAB1 (JX1_IN C/D) AND RECEIVES THE RETURN FROM CAB3 (JX2_OUT C/D). INTER-CABINET
  LEGS ARE RACK-TO-RACK FIELD WIRING; ROUTE THE RETURN LEG IN A SEPARATE RACEWAY FROM THE SEND LEG (NFPA 72 CLASS A SEPARATION).
  REV K 24VDC (R-08/R-09): RAIL A = PSU1+PSU2 > RM1 > UPS1 (EMS/NETWORK/IO/FIRE-TRIP). RAIL B = PSU3+PSU4 > RM2 (MBMU + ETH MODULES).
  SUPPLY HEALTH: RM1/RM2 DC-OK + UPS1 BUFFER CONTACTS > IO1 DI3/DI4/DI5 - FIRST FAILURE ANNUNCIATES AT THE EMS. CONTACT OPTION PER DATASHEET AT PROCUREMENT.
  FIRE ALARM BRANCH (R-02): CB9 15A 1P OFF SEC L1 FEEDS FACP1 + PSN1 AND NO OTHER LOAD (NEC 760.121(B)); RED HANDLE + LOCK-ON +
  'FIRE ALARM CIRCUIT' MARKING + OCPD LOCATION PLACARD AT FACP1. NOTE: BRANCH DERIVES FROM T2/CPT - OPENING Q1 PUTS FACP ON BATTERY.
  ENCLOSURE CLIMATE (R-03): AC1 230V ON CB10 (LOCKABLE = 440.14 DISCONNECT), HTR1 100W VIA TH1 ON CB11 - BOTH FROM 380Y AUX, NOT THE CPT.
  FINAL A/C SELECTION AT IFC FROM THE HEAT-BALANCE SHEET (SCHEDULE PKG); T2 PER-LEG VA CENSUS IN SCHEDULE PKG.
  AS-BUILT PINOUT (CARSON, COORDINATE-VERIFIED x3 CLUSTERS): MBMU J3.1-17 JUMPER, J3.2 +24V, J3.19 0V; J5.13/14 CAN+/- TO CABINET;
  J5.29/30 > J902.6/5 (PAIR A); J5.33/34 > J902.22/21 (PAIR B) WITH 60R CRIMPED AT MBMU END. 20AWG ALL CONNECTOR CRIMPS. J902 9-12 + 10-11 JUMPERS.
  WIRE SPECIFICATION (PER CATL EXTERNAL WIRING DIAGRAM + MX34JAHL CONNECTOR MANUAL + EnerOne+ R08306P05L31 SPEC):
  480V: 8AWG THHN/MTW CU (40A CKT), TAPS 14AWG, SPD LEADS 10AWG <=0.5M. AUX FIELD TO CABINETS: AWG10 ADAPTER CABLES PER CATL
  (JXH1: A/B CHILLER 3KW - CATL FIGURES CONFLICT: SPEC <=12.5A <1MS INRUSH, EW DIAGRAM 31A SURGE, '10A' RATING - RLA/MCA/MOCP AT RFI-002;
  CB3/5/7 = 20A C-CURVE (REV J): HOLDS 13.6A CONT + EITHER INRUSH FIGURE; NEC 440.22(A) CEILING 175% X RLA - VALID FOR RLA >= 11.5A, CONFIRM AT RFI-002.
  PANEL AUX: 10AWG HVAC (REV J) / 14AWG BMS (TRANSITION TO CATL AWG10 ADAPTER AT TB2-TB4). AUX FEEDER: 240.21(B)(2) 25-FT TAP, AMPACITY >= 1/3
  OF THE KEHUA OUTPUT BREAKER, TERMINATES IN Q2 = SINGLE OCPD; ANY KEHUA BREAKER > 30A REQUIRES FEEDER UPSIZE FROM AWG10 (RFI-001).
  MBMU+ETH RUN ON 24VDC FROM THIS PANEL; RACK-INTERNAL BMS (SBMU/CSC) ON 220V AUX VIA IN-RACK ACDC; CHILLER DIRECT 220V AUX.
  120/240V CTRL: 14AWG MTW. 24VDC: 16AWG MTW. CAN: 0.5MM2/AWG20 TWISTED-PAIR SHIELDED, TWIST PITCH 20-30MM, SINGLE-POINT GROUND,
  <=30M MBMU-TO-120R-END-TERMINAL (ELSE CANBRIDGE); CANH=YELLOW CANL=GREEN; SHIELD CRIMP M34S75C4F3, SIGNAL CRIMPS M34S75C4F2 (JAE MX34 SOP (REV K R-44)).
  ETHERNET ETH-TO-EMS/SWITCH: CAT6A MIN (CATL CHECKLIST CITES CAT7), SHIELDED; ETH MODULE HOUSING BONDED TO PE (CATL CHECK).
  FIRE: FPL 14-18AWG PER POTTER/NFPA72; RELEASING CIRCUITS FPL 14AWG. CT LEADS: 18AWG TWISTED. PE: 8AWG CU MIN, EGC PER 250.122;
  RACK GROUND >=50MM2 CU, M8 @ 10N.M (FIELD, BY OTHERS). HARNESS COLORS PER CATL: +24 RED / 0V BLACK / L RED / N BLACK / OTHERS WHITE.
  TB TYPES: SLC/SUP/CAN-SIGNAL/CT TERMINALS = INSULATED FEED-THROUGH (PHOENIX UK 5 N / UT 4) - NOT USLKG GROUND BLOCKS;
  USLKG (RAIL-BONDED) ONLY AT THE 3 CAN SHIELD POLES = SINGLE-POINT SHIELD GROUND (SB1-3). TB11 CT LANDING = UT 4 FEED-THROUGH, 18 POLES.
  R1-R3 60R (CARSON AS-BUILT): AT COMMISSIONING MEASURE J902.21/22: EXPECT ~60R; IF ~30R, REMOVE CRIMPED 60R (OVER-TERMINATION). ICD ITEM.
  AUX SOURCE: KEHUA CABINET-375 INTEGRATED 30KVA 480/380Y TX + 3 OUTPUT BREAKERS (REV I). EXACTLY ONE N-G BOND PER SEPARATELY DERIVED
  SYSTEM: BD1 AT THE CPT (IN PANEL); THE 380Y AUX SYSTEM BONDS AT THE KEHUA TX INSIDE THE PCS CABINET (CONFIRM AT RFI-001) - NEVER BOTH ENDS.
  TWO SOURCES OF SUPPLY (480V Q1 + 380Y KEHUA Q2) - NEC 409.110 WARNING LABEL; FULL LABEL SCHEDULE IN SCHEDULE PKG (409.110/409.22(B)/110.16/ESS).
  OPEN ITEMS AT IFC: PE STAMP; SCCR (UL508A SB4, SCHEDULE PKG WORKSHEET); RFI-001 KEHUA / RFI-002 CATL-POTTER ANSWERS; NFPA 72 SECONDARY
  CALC SIGN-OFF (WORKSHEET NFPA72-W1: 4.73AH FACP + PSN SEPARATE; CATL 2H SOUND/LIGHT TERM WITH AHJ); BATTALION VLAN; CLIENT DEVIATIONS
  (SINGLE EG4115 METER / SINGLE MANAGED SWITCH); WIRE NUMBERS AT FAB RELEASE. PROPRIETARY - STR MEDICAL. FOR REVIEW ONLY - PE REVIEW REQUIRED.
- z1Power - Sugarland BESS - COMPLETE PANEL SCHEMATIC - REV K (SIMPLIFIED) - DWG Z1SL-ALT-002
- STR Medical  /  PROPRIETARY - STR MEDICAL
- FOR REVIEW ONLY - NOT FOR CONSTRUCTION - PE REVIEW REQUIRED
- Hybrid net-label edition: AC power train drawn; long signal runs as labelled stubs; PE/DC_COM/24V_UPS/24V_RMS/24V_ETH as power ports
- Generated from the verified Rev K design database (174-net golden diff PASS)  /  2026-08-09

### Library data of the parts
AC1#2 = ENCL_AC_230V: Enclosure A/C, 230V, ~1500 BTU/h [final per heat balance]; Manufacturer: Pfannenberg/nVent; PartNumber: DTS 3141 230V class [SELECT AT IFC]
BAT1#2 BAT2#2 = BATT_12V: Battery 12V 8Ah SLA (FACP); Manufacturer: Power-Sonic; PartNumber: PS-1280
BAT3#2 BAT4#2 = BATT_12V: Battery 12V 8Ah SLA (PSN1, REV K); Manufacturer: Power-Sonic; PartNumber: PS-1280
BD1#2 = BOND_JUMPER: N-G bond kit #8 AWG Cu + lugs + label; Manufacturer: Ilsco; PartNumber: [kit per shop practice]
CB1#2 = CB_3P: SPD breaker 30A 3P UL489 DIN, 480Y/277V, 10kA min; Manufacturer: ABB; PartNumber: SU203M-K30 [PROPOSED - CONFIRM AT PROCUREMENT]
CB2#2 = CB_2P: Control main breaker 2P 15A UL489 DIN, 240V, 10kA; Manufacturer: ABB; PartNumber: SU202M-C15 [PROPOSED]
CB3#2 CB5#2 CB7#2 = CB_1P: Branch breaker 20A 1P UL489, C-curve, 480Y/277V, 10kA; Manufacturer: ABB; PartNumber: SU201M-C20 [PROPOSED - REV K R-04]
CB4#2 CB6#2 CB8#2 = CB_1P: Branch breaker 6A 1P UL489, C-curve, 480Y/277V, 10kA; Manufacturer: ABB; PartNumber: SU201M-C6 [PROPOSED - REV K R-04]
CB9#2 = CB_1P: FIRE ALARM branch breaker 1P 15A UL489, RED handle + lock-on; Manufacturer: ABB; PartNumber: SU201M-C15 + S2C-H6R red + MSL-2 lock [PROPOSED]
CB10#2 = CB_1P: Enclosure A/C breaker 10A 1P UL489, 480Y/277V, lockable; Manufacturer: ABB; PartNumber: SU201M-C10 + MSL-2 [PROPOSED]
CB11#2 = CB_1P: Enclosure heater breaker 6A 1P UL489, 480Y/277V; Manufacturer: ABB; PartNumber: SU201M-C6 [PROPOSED]
CPU1#2 CPU2#2 = MOXA_UC2222A: EMS computer, Arm DIN-rail, Linux (Battalion image); Manufacturer: Moxa; PartNumber: UC-2222A-T-US
DS1#2 = REL_SERVICE_DISC: Releasing service disconnect, 3-ckt, lockable, position-supervised; Manufacturer: Potter/equal; PartNumber: [CONFIRM LISTED DEVICE AT ICD]
EM1#2 EM2#2 EM3#2 = CATL_ETH_ASBUILT: ETH comms module
F1#2 F2#2 F3#2 = FUSE_KLKR: Fuse, Class CC fast-acting 1A (meter taps); Manufacturer: Littelfuse; PartNumber: KLKR-1
F4#2 F5#2 = FUSE_KLKR: Fuse, Class CC TIME-DELAY 3A (CPT primary, 450.3(B) <=3A); Manufacturer: Littelfuse; PartNumber: FNQ-R-3
F6#2 F7#2 = FUSE_KLKR: Fuse, Class CC time-delay 4A (PSU1/PSU2 primaries); Manufacturer: Littelfuse
F9#2 F19#2 = FUSE_KLKR: Fuse, Class CC time-delay 6A (PSU3/PSU4 primaries); Manufacturer: Littelfuse
F10#2 F11#2 F12#2 F13#2 F14#2 F15#2 F16#2 F17#2 F18#2 = FUSE_KLKR: Fuse, Class CC: KLKR-2 x7 (CPU1/2, BMS1-3, IO, ETH), KLKR-3 x1 (network), KLKR-1 x1 (fire trip loop); Manufacturer: Littelfuse; PartNumber: KLKR-1/-2/-3 per schedule
FACP1#2 = POTTER_ARC100: Addressable releasing FACP, 100-pt; Manufacturer: Potter
GB1#2 = PE_GROUND_BUS: Ground bus bar kit + lugs; Manufacturer: Ilsco/Panduit; PartNumber: IGB-14 class [PROPOSED]
HTR1#2 = ENCL_HEATER: Anti-condensation heater 100W + NC thermostat; Manufacturer: Stego; PartNumber: HGL 046 + KTO 011 [PROPOSED]
IO1#2 = IOLOGIK_E1214: Remote I/O, 6 DI / 6 relay DO, Ethernet; Manufacturer: Moxa
K1#2 = RELAY_2FORMC_24V: Interposing relay, 2 Form C, 24VDC coil, DIN (PCS fire trip); Manufacturer: Phoenix Contact; PartNumber: RIF-1-RPT-LDP-24DC [PROPOSED]
M1#2 = EGAUGE_EG4115: Revenue meter, 15 CT inputs, Ethernet; PartNumber: EG4115 (Core)
MBMU1#2 MBMU2#2 MBMU3#2 = CATL_MBMU_ASBUILT: Master BMS unit
MM1#2 MM2#2 MM3#2 = SLC_MONITOR_MOD: SLC monitor module (DS1 position / PSN trouble / manual release); Manufacturer: Potter; PartNumber: PAD100-IM [CONFIRM]
PSN1#2 = POTTER_PSN1000: Listed releasing/aux power supply 10A (3A/ckt); Manufacturer: Potter
PSU1#2 PSU2#2 = NDR75_24: PSU 24VDC 75W DIN (rail A); Manufacturer: Mean Well
PSU3#2 PSU4#2 = NDR75_24: PSU 24VDC 240W/10A DIN (rail B, REV K R-08: now REDUNDANT pair); Manufacturer: Mean Well
PT1#2 = PT_3PH: Potential transformer set, 480:120, metering class; Manufacturer: Functional Devices/ITI; PartNumber: [VERIFY ratio per Carson]
Q1#2 = DISC_3P_40A: Main disconnect breaker 40A 3P UL489 DIN, 480V, marked IR; Manufacturer: Phoenix Contact; PartNumber: TMC S3D (per Carson) [VERIFY AIC vs SCCR study]
Q2#2 = DISC_3P_40A: Aux main breaker 25A 3P, 480Y/277V UL489, marked IR; Manufacturer: ABB; PartNumber: SU203M-C25 [PROPOSED]
R1#2 R2#2 R3#2 = RESISTOR: Termination resistor 60R 0.25W - crimped into MBMU J5.33/34
R4#2 R5#2 R6#2 R7#2 R8#2 R10#2 R11#2 R12#2 = RESISTOR_L: EOL devices: NAC(R4), SUP1-3(R5-7), abort(R8), MM inputs(R10,R12), man-rel(R11); Manufacturer: Potter; PartNumber: EOLD 3005012
RM1#2 = DRDN20_24_OK: Redundancy module 20A + DC-OK contact; Manufacturer: Mean Well; PartNumber: DRDN20-24 [CONFIRM DC-OK contact option]
RM2#2 = DRDN20_24_OK: Redundancy module 40A + DC-OK contact (REV K); Manufacturer: Mean Well; PartNumber: DRDN40-24 [CONFIRM DC-OK contact option]
SB1#2 SB2#2 SB3#2 = BOND_JUMPER: TB, USLKG 5 ground block - CAN SHIELD POLES ONLY; Manufacturer: Phoenix Contact; PartNumber: USLKG 5
SIR1#2 = SIREN: Siren, 24VDC, panel mount; Manufacturer: Potter; PartNumber: SQ-24 class [PROPOSED]
SPD1#2 = SPD_T2_480Y277: Type 2 SPD, 480/277Y, NEMA panel mount; Manufacturer: Raycap/Eaton; PartNumber: [VERIFY P/N + In/AIC]
STB1#2 = STROBE_HT8AEHA: Strobe/horn; Manufacturer: Eaton; PartNumber: HT8AEHA (per Carson)
SW1#2 = EDS4014_MANAGED: Managed switch 14-port, VLAN, DIN; Manufacturer: Moxa; PartNumber: EDS-4014 [VERIFY variant w/ Battalion]
T2#2 = CPT_480_120240: Control power TX 500VA 480>120/240, encapsulated; Manufacturer: SolaHD/HPS; PartNumber: E500 class [VERIFY]
TB1#2 TB13#2 = TB_5: Feed-through TB, UT 6 (grey) + UT 6-PE (gn/ye); Manufacturer: Phoenix Contact; PartNumber: UT 6 / UT 6-PE
TB2#2 TB3#2 TB4#2 = TB_5L: Feed-through TB, UT 6 + UT 6-PE, cabinet aux circuits; Manufacturer: Phoenix Contact; PartNumber: UT 6 / UT 6-PE
TB5#2 TB6#2 TB7#2 = TB_3L: TB, UK 5 N insulated feed-through (CAN H/L); Manufacturer: Phoenix Contact; PartNumber: UK 5 N
TB8#2 TB9#2 TB15#2 TB16#2 = TB_2L: TB, UK 5 N insulated feed-through (SLC send/return, suppression, abort, man-rel, EPO); Manufacturer: Phoenix Contact; PartNumber: UK 5 N
TB11#2 = TB_18L: TB, UT 4 feed-through (CT landing, 18 pos + spares); Manufacturer: Phoenix Contact; PartNumber: UT 4
TB14#2 = TB_6L: TB, UK 5 N insulated feed-through (SLC send/return, suppression, abort, man-rel, EPO); Manufacturer: Phoenix Contact; PartNumber: UK 5 N
TB23#2 = TB_4L: TB, UK 5 N insulated feed-through (SLC send/return, suppression, abort, man-rel, EPO); Manufacturer: Phoenix Contact; PartNumber: UK 5 N
TH1#2 = THERMOSTAT_NC: Anti-condensation heater 100W + NC thermostat; Manufacturer: Stego; PartNumber: HGL 046 + KTO 011 [PROPOSED]
UPS1#2 = QUINTCAP_4KJ: DC UPS supercap 4kJ 24VDC + signaling contact; Manufacturer: Phoenix Contact; PartNumber: QUINT4-CAP/24DC/5/4KJ
X1#2 = FIELD_480V_SOURCE
X2#2 X3#2 X4#2 X5#2 = FIELD_ETH_DEV
X6#2 X7#2 X8#2 = FIELD_CATL_AUX
X9#2 X10#2 X11#2 = FIELD_CATL_CAN
X12#2 = FIELD_CATL_SLC_IN
X13#2 = FIELD_CATL_SUPONLY
X14#2 = FIELD_CATL_SLC_OUT
X15#2 X16#2 X17#2 = FIELD_CT_SET: Split-core CT, 333mV UL2808 (PoI/Solar/BESS L1-L3, field sets); Manufacturer: eGauge; PartNumber: ECS series [size per conductor]
X18#2 = KEHUA_AUX_SRC: Aux 380Y/220V source = Kehua PCS Cabinet-375 internal 30kVA 480/380 TX + 3 output breakers
X23#2 = FIELD_KEHUA_EPO
X24#2 = FIELD_ABORT_STN: Abort station, constant-pressure, guarded (FIELD at cabinet line-up); Manufacturer: Potter; PartNumber: APS-1 class [CONFIRM AT ICD]
X25#2 = FIELD_MANREL_STN: Manual release station, dual-action (FIELD); Manufacturer: Potter; PartNumber: RMS-1T class [CONFIRM AT ICD]

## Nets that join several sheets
24V_ETH: Z1-Sugarland (EM1#1.1 EM2#1.1 EM3#1.1 F17#1.2), Z1-Sugarland-Simplified (EM1#2.1 EM2#2.1 EM3#2.1 F17#2.2)
24V_RMS: Z1-Sugarland (5 pins), Z1-Sugarland-Simplified (5 pins)
24V_UPS: Z1-Sugarland (6 pins), Z1-Sugarland-Simplified (6 pins)
DC_COM: Z1-Sugarland (17 pins), Z1-Sugarland-Simplified (17 pins)
PE: Z1-Sugarland (27 pins), Z1-Sugarland-Simplified (27 pins)
24V_BMS1: Z1-Sugarland (F13#1.2 MBMU1#1.3), Z1-Sugarland-Simplified (F13#2.2 MBMU1#2.3)
24V_BMS2: Z1-Sugarland (F14#1.2 MBMU2#1.3), Z1-Sugarland-Simplified (F14#2.2 MBMU2#2.3)
24V_BMS3: Z1-Sugarland (F15#1.2 MBMU3#1.3), Z1-Sugarland-Simplified (F15#2.2 MBMU3#2.3)
24V_BUS: Z1-Sugarland (RM1#1.3 UPS1#1.1), Z1-Sugarland-Simplified (RM1#2.3 UPS1#2.1)
24V_EMS_A: Z1-Sugarland (CPU1#1.1 F10#1.2), Z1-Sugarland-Simplified (CPU1#2.1 F10#2.2)
24V_EMS_B: Z1-Sugarland (CPU2#1.1 F11#1.2), Z1-Sugarland-Simplified (CPU2#2.1 F11#2.2)
24V_IO: Z1-Sugarland (5 pins), Z1-Sugarland-Simplified (5 pins)
24V_NET: Z1-Sugarland (F12#1.2 SW1#1.1), Z1-Sugarland-Simplified (F12#2.2 SW1#2.1)
24V_PSU1: Z1-Sugarland (PSU1#1.4 RM1#1.1), Z1-Sugarland-Simplified (PSU1#2.4 RM1#2.1)
24V_PSU2: Z1-Sugarland (PSU2#1.4 RM1#1.2), Z1-Sugarland-Simplified (PSU2#2.4 RM1#2.2)
24V_PSU3: Z1-Sugarland (PSU3#1.4 RM2#1.1), Z1-Sugarland-Simplified (PSU3#2.4 RM2#2.1)
24V_PSU4: Z1-Sugarland (PSU4#1.4 RM2#1.2), Z1-Sugarland-Simplified (PSU4#2.4 RM2#2.2)
480_L1: Z1-Sugarland (Q1#1.1 TB1#1.1 X1#1.1), Z1-Sugarland-Simplified (Q1#2.1 TB1#2.1 X1#2.1)
480_L2: Z1-Sugarland (Q1#1.2 TB1#1.2 X1#1.2), Z1-Sugarland-Simplified (Q1#2.2 TB1#2.2 X1#2.2)
480_L3: Z1-Sugarland (Q1#1.3 TB1#1.3 X1#1.3), Z1-Sugarland-Simplified (Q1#2.3 TB1#2.3 X1#2.3)
480_N: Z1-Sugarland (PT1#1.4 SPD1#1.4 TB1#1.4 X1#1.4), Z1-Sugarland-Simplified (PT1#2.4 SPD1#2.4 TB1#2.4 X1#2.4)
ABORT_N: Z1-Sugarland (FACP1#1.7 R8#1.2 TB15#1.2 X24#1.2), Z1-Sugarland-Simplified (FACP1#2.7 R8#2.2 TB15#2.2 X24#2.2)
ABORT_P: Z1-Sugarland (FACP1#1.6 R8#1.1 TB15#1.1 X24#1.1), Z1-Sugarland-Simplified (FACP1#2.6 R8#2.1 TB15#2.1 X24#2.1)
ACU_L: Z1-Sugarland (AC1#1.1 CB10#1.2), Z1-Sugarland-Simplified (AC1#2.1 CB10#2.2)
AUX_L1: Z1-Sugarland (CB3#1.1 CB4#1.1 CB10#1.1 Q2#1.4), Z1-Sugarland-Simplified (CB3#2.1 CB4#2.1 CB10#2.1 Q2#2.4)
AUX_L2: Z1-Sugarland (CB5#1.1 CB6#1.1 CB11#1.1 Q2#1.5), Z1-Sugarland-Simplified (CB5#2.1 CB6#2.1 CB11#2.1 Q2#2.5)
AUX_L3: Z1-Sugarland (CB7#1.1 CB8#1.1 Q2#1.6), Z1-Sugarland-Simplified (CB7#2.1 CB8#2.1 Q2#2.6)
AUX_N: Z1-Sugarland (16 pins), Z1-Sugarland-Simplified (16 pins)
AUXF_L1: Z1-Sugarland (Q2#1.1 TB13#1.1 X18#1.1), Z1-Sugarland-Simplified (Q2#2.1 TB13#2.1 X18#2.1)
AUXF_L2: Z1-Sugarland (Q2#1.2 TB13#1.2 X18#1.2), Z1-Sugarland-Simplified (Q2#2.2 TB13#2.2 X18#2.2)
AUXF_L3: Z1-Sugarland (Q2#1.3 TB13#1.3 X18#1.3), Z1-Sugarland-Simplified (Q2#2.3 TB13#2.3 X18#2.3)
BATT_MID: Z1-Sugarland (BAT1#1.2 BAT2#1.1), Z1-Sugarland-Simplified (BAT1#2.2 BAT2#2.1)
BATT_N: Z1-Sugarland (BAT2#1.2 FACP1#1.5), Z1-Sugarland-Simplified (BAT2#2.2 FACP1#2.5)
BATT_P: Z1-Sugarland (BAT1#1.1 FACP1#1.4), Z1-Sugarland-Simplified (BAT1#2.1 FACP1#2.4)
C1_BMS_L: Z1-Sugarland (CB4#1.2 TB2#1.3 X6#1.3), Z1-Sugarland-Simplified (CB4#2.2 TB2#2.3 X6#2.3)
C1_HVAC_L: Z1-Sugarland (CB3#1.2 TB2#1.1 X6#1.1), Z1-Sugarland-Simplified (CB3#2.2 TB2#2.1 X6#2.1)
C2_BMS_L: Z1-Sugarland (CB6#1.2 TB3#1.3 X7#1.3), Z1-Sugarland-Simplified (CB6#2.2 TB3#2.3 X7#2.3)
C2_HVAC_L: Z1-Sugarland (CB5#1.2 TB3#1.1 X7#1.1), Z1-Sugarland-Simplified (CB5#2.2 TB3#2.1 X7#2.1)
C3_BMS_L: Z1-Sugarland (CB8#1.2 TB4#1.3 X8#1.3), Z1-Sugarland-Simplified (CB8#2.2 TB4#2.3 X8#2.3)
C3_HVAC_L: Z1-Sugarland (CB7#1.2 TB4#1.1 X8#1.1), Z1-Sugarland-Simplified (CB7#2.2 TB4#2.1 X8#2.1)
CAN1_H: Z1-Sugarland (MBMU1#1.7 TB5#1.1 X9#1.1), Z1-Sugarland-Simplified (MBMU1#2.7 TB5#2.1 X9#2.1)
CAN1_L: Z1-Sugarland (MBMU1#1.8 TB5#1.2 X9#1.2), Z1-Sugarland-Simplified (MBMU1#2.8 TB5#2.2 X9#2.2)
CAN1_SHD: Z1-Sugarland (SB1#1.1 TB5#1.3 X9#1.3), Z1-Sugarland-Simplified (SB1#2.1 TB5#2.3 X9#2.3)
CAN2_H: Z1-Sugarland (MBMU2#1.7 TB6#1.1 X10#1.1), Z1-Sugarland-Simplified (MBMU2#2.7 TB6#2.1 X10#2.1)
CAN2_L: Z1-Sugarland (MBMU2#1.8 TB6#1.2 X10#1.2), Z1-Sugarland-Simplified (MBMU2#2.8 TB6#2.2 X10#2.2)
CAN2_SHD: Z1-Sugarland (SB2#1.1 TB6#1.3 X10#1.3), Z1-Sugarland-Simplified (SB2#2.1 TB6#2.3 X10#2.3)
CAN3_H: Z1-Sugarland (MBMU3#1.7 TB7#1.1 X11#1.1), Z1-Sugarland-Simplified (MBMU3#2.7 TB7#2.1 X11#2.1)
CAN3_L: Z1-Sugarland (MBMU3#1.8 TB7#1.2 X11#1.2), Z1-Sugarland-Simplified (MBMU3#2.8 TB7#2.2 X11#2.2)
CAN3_SHD: Z1-Sugarland (SB3#1.1 TB7#1.3 X11#1.3), Z1-Sugarland-Simplified (SB3#2.1 TB7#2.3 X11#2.3)
CPT_PRI_1: Z1-Sugarland (F4#1.2 T2#1.1), Z1-Sugarland-Simplified (F4#2.2 T2#2.1)
CPT_PRI_2: Z1-Sugarland (F5#1.2 T2#1.2), Z1-Sugarland-Simplified (F5#2.2 T2#2.2)
CT_BESS_1M: Z1-Sugarland (M1#1.19 TB11#1.14 X17#1.2), Z1-Sugarland-Simplified (M1#2.19 TB11#2.14 X17#2.2)
CT_BESS_1P: Z1-Sugarland (M1#1.18 TB11#1.13 X17#1.1), Z1-Sugarland-Simplified (M1#2.18 TB11#2.13 X17#2.1)
CT_BESS_2M: Z1-Sugarland (M1#1.21 TB11#1.16 X17#1.4), Z1-Sugarland-Simplified (M1#2.21 TB11#2.16 X17#2.4)
CT_BESS_2P: Z1-Sugarland (M1#1.20 TB11#1.15 X17#1.3), Z1-Sugarland-Simplified (M1#2.20 TB11#2.15 X17#2.3)
CT_BESS_3M: Z1-Sugarland (M1#1.23 TB11#1.18 X17#1.6), Z1-Sugarland-Simplified (M1#2.23 TB11#2.18 X17#2.6)
CT_BESS_3P: Z1-Sugarland (M1#1.22 TB11#1.17 X17#1.5), Z1-Sugarland-Simplified (M1#2.22 TB11#2.17 X17#2.5)
CT_POI_1M: Z1-Sugarland (M1#1.7 TB11#1.2 X15#1.2), Z1-Sugarland-Simplified (M1#2.7 TB11#2.2 X15#2.2)
CT_POI_1P: Z1-Sugarland (M1#1.6 TB11#1.1 X15#1.1), Z1-Sugarland-Simplified (M1#2.6 TB11#2.1 X15#2.1)
CT_POI_2M: Z1-Sugarland (M1#1.9 TB11#1.4 X15#1.4), Z1-Sugarland-Simplified (M1#2.9 TB11#2.4 X15#2.4)
CT_POI_2P: Z1-Sugarland (M1#1.8 TB11#1.3 X15#1.3), Z1-Sugarland-Simplified (M1#2.8 TB11#2.3 X15#2.3)
CT_POI_3M: Z1-Sugarland (M1#1.11 TB11#1.6 X15#1.6), Z1-Sugarland-Simplified (M1#2.11 TB11#2.6 X15#2.6)
CT_POI_3P: Z1-Sugarland (M1#1.10 TB11#1.5 X15#1.5), Z1-Sugarland-Simplified (M1#2.10 TB11#2.5 X15#2.5)
CT_SOL_1M: Z1-Sugarland (M1#1.13 TB11#1.8 X16#1.2), Z1-Sugarland-Simplified (M1#2.13 TB11#2.8 X16#2.2)
CT_SOL_1P: Z1-Sugarland (M1#1.12 TB11#1.7 X16#1.1), Z1-Sugarland-Simplified (M1#2.12 TB11#2.7 X16#2.1)
CT_SOL_2M: Z1-Sugarland (M1#1.15 TB11#1.10 X16#1.4), Z1-Sugarland-Simplified (M1#2.15 TB11#2.10 X16#2.4)
CT_SOL_2P: Z1-Sugarland (M1#1.14 TB11#1.9 X16#1.3), Z1-Sugarland-Simplified (M1#2.14 TB11#2.9 X16#2.3)
CT_SOL_3M: Z1-Sugarland (M1#1.17 TB11#1.12 X16#1.6), Z1-Sugarland-Simplified (M1#2.17 TB11#2.12 X16#2.6)
CT_SOL_3P: Z1-Sugarland (M1#1.16 TB11#1.11 X16#1.5), Z1-Sugarland-Simplified (M1#2.16 TB11#2.11 X16#2.5)
CTRL_L1: Z1-Sugarland (CB2#1.3 F6#1.1 F19#1.1), Z1-Sugarland-Simplified (CB2#2.3 F6#2.1 F19#2.1)
CTRL_L2: Z1-Sugarland (CB2#1.4 F7#1.1 F9#1.1), Z1-Sugarland-Simplified (CB2#2.4 F7#2.1 F9#2.1)
DS1_MON_A: Z1-Sugarland (DS1#1.7 MM1#1.3 R10#1.1), Z1-Sugarland-Simplified (DS1#2.7 MM1#2.3 R10#2.1)
DS1_MON_B: Z1-Sugarland (DS1#1.8 MM1#1.4 R10#1.2), Z1-Sugarland-Simplified (DS1#2.8 MM1#2.4 R10#2.2)
EPO_1A: Z1-Sugarland (K1#1.3 TB23#1.1 X23#1.1), Z1-Sugarland-Simplified (K1#2.3 TB23#2.1 X23#2.1)
EPO_1B: Z1-Sugarland (K1#1.5 TB23#1.2 X23#1.2), Z1-Sugarland-Simplified (K1#2.5 TB23#2.2 X23#2.2)
EPO_2A: Z1-Sugarland (K1#1.6 TB23#1.3 X23#1.3), Z1-Sugarland-Simplified (K1#2.6 TB23#2.3 X23#2.3)
EPO_2B: Z1-Sugarland (K1#1.7 TB23#1.4 X23#1.4), Z1-Sugarland-Simplified (K1#2.7 TB23#2.4 X23#2.4)
ETH_CPU1_LAN: Z1-Sugarland (CPU1#1.4 SW1#1.6), Z1-Sugarland-Simplified (CPU1#2.4 SW1#2.6)
ETH_CPU1_WAN: Z1-Sugarland (CPU1#1.3 SW1#1.4), Z1-Sugarland-Simplified (CPU1#2.3 SW1#2.4)
ETH_CPU2_LAN: Z1-Sugarland (CPU2#1.4 SW1#1.7), Z1-Sugarland-Simplified (CPU2#2.4 SW1#2.7)
ETH_CPU2_WAN: Z1-Sugarland (CPU2#1.3 SW1#1.5), Z1-Sugarland-Simplified (CPU2#2.3 SW1#2.5)
ETH_IO: Z1-Sugarland (IO1#1.10 SW1#1.9), Z1-Sugarland-Simplified (IO1#2.10 SW1#2.9)
ETH_METER: Z1-Sugarland (M1#1.5 SW1#1.8), Z1-Sugarland-Simplified (M1#2.5 SW1#2.8)
ETH_MOD1: Z1-Sugarland (EM1#1.11 SW1#1.13), Z1-Sugarland-Simplified (EM1#2.11 SW1#2.13)
ETH_MOD2: Z1-Sugarland (EM2#1.11 SW1#1.14), Z1-Sugarland-Simplified (EM2#2.11 SW1#2.14)
ETH_MOD3: Z1-Sugarland (EM3#1.11 SW1#1.15), Z1-Sugarland-Simplified (EM3#2.11 SW1#2.15)
ETH_PCS1: Z1-Sugarland (SW1#1.10 X3#1.1), Z1-Sugarland-Simplified (SW1#2.10 X3#2.1)
ETH_PCS2: Z1-Sugarland (SW1#1.11 X4#1.1), Z1-Sugarland-Simplified (SW1#2.11 X4#2.1)
ETH_PCS3: Z1-Sugarland (SW1#1.12 X5#1.1), Z1-Sugarland-Simplified (SW1#2.12 X5#2.1)
ETH_WAN_UPLINK: Z1-Sugarland (SW1#1.3 X2#1.1), Z1-Sugarland-Simplified (SW1#2.3 X2#2.1)
FACP_AC_L: Z1-Sugarland (CB9#1.2 FACP1#1.1 PSN1#1.1), Z1-Sugarland-Simplified (CB9#2.2 FACP1#2.1 PSN1#2.1)
FACP_ALM: Z1-Sugarland (FACP1#1.20 IO1#1.3), Z1-Sugarland-Simplified (FACP1#2.20 IO1#2.3)
FACP_COM: Z1-Sugarland (FACP1#1.21 FACP1#1.23 FACP1#1.25 IO1#1.6), Z1-Sugarland-Simplified (FACP1#2.21 FACP1#2.23 FACP1#2.25 IO1#2.6)
FACP_SUP: Z1-Sugarland (FACP1#1.22 IO1#1.4), Z1-Sugarland-Simplified (FACP1#2.22 IO1#2.4)
FACP_TRB: Z1-Sugarland (FACP1#1.24 IO1#1.5), Z1-Sugarland-Simplified (FACP1#2.24 IO1#2.5)
FT_A: Z1-Sugarland (F18#1.2 FACP1#1.26), Z1-Sugarland-Simplified (F18#2.2 FACP1#2.26)
FT_B: Z1-Sugarland (FACP1#1.27 K1#1.1), Z1-Sugarland-Simplified (FACP1#2.27 K1#2.1)
HTR_FEED: Z1-Sugarland (CB11#1.2 TH1#1.1), Z1-Sugarland-Simplified (CB11#2.2 TH1#2.1)
HTR_L: Z1-Sugarland (HTR1#1.1 TH1#1.2), Z1-Sugarland-Simplified (HTR1#2.1 TH1#2.2)
MAIN_L1: Z1-Sugarland (CB1#1.1 F1#1.1 F4#1.1 Q1#1.4), Z1-Sugarland-Simplified (CB1#2.1 F1#2.1 F4#2.1 Q1#2.4)
MAIN_L2: Z1-Sugarland (CB1#1.2 F2#1.1 F5#1.1 Q1#1.5), Z1-Sugarland-Simplified (CB1#2.2 F2#2.1 F5#2.1 Q1#2.5)
MAIN_L3: Z1-Sugarland (CB1#1.3 F3#1.1 Q1#1.6), Z1-Sugarland-Simplified (CB1#2.3 F3#2.1 Q1#2.6)
MBMU1_C2A: Z1-Sugarland (EM1#1.5 MBMU1#1.11 R1#1.1), Z1-Sugarland-Simplified (EM1#2.5 MBMU1#2.11 R1#2.1)
MBMU1_C2B: Z1-Sugarland (EM1#1.6 MBMU1#1.12 R1#1.2), Z1-Sugarland-Simplified (EM1#2.6 MBMU1#2.12 R1#2.2)
MBMU2_C2A: Z1-Sugarland (EM2#1.5 MBMU2#1.11 R2#1.1), Z1-Sugarland-Simplified (EM2#2.5 MBMU2#2.11 R2#2.1)
MBMU2_C2B: Z1-Sugarland (EM2#1.6 MBMU2#1.12 R2#1.2), Z1-Sugarland-Simplified (EM2#2.6 MBMU2#2.12 R2#2.2)
MBMU3_C2A: Z1-Sugarland (EM3#1.5 MBMU3#1.11 R3#1.1), Z1-Sugarland-Simplified (EM3#2.5 MBMU3#2.11 R3#2.1)
MBMU3_C2B: Z1-Sugarland (EM3#1.6 MBMU3#1.12 R3#1.2), Z1-Sugarland-Simplified (EM3#2.6 MBMU3#2.12 R3#2.2)
MREL_N: Z1-Sugarland (MM2#1.4 R11#1.2 TB16#1.2 X25#1.2), Z1-Sugarland-Simplified (MM2#2.4 R11#2.2 TB16#2.2 X25#2.2)
MREL_P: Z1-Sugarland (MM2#1.3 R11#1.1 TB16#1.1 X25#1.1), Z1-Sugarland-Simplified (MM2#2.3 R11#2.1 TB16#2.1 X25#2.1)
MTR_L1: Z1-Sugarland (M1#1.1 PT1#1.5), Z1-Sugarland-Simplified (M1#2.1 PT1#2.5)
MTR_L2: Z1-Sugarland (M1#1.2 PT1#1.6), Z1-Sugarland-Simplified (M1#2.2 PT1#2.6)
MTR_L3: Z1-Sugarland (M1#1.3 PT1#1.7), Z1-Sugarland-Simplified (M1#2.3 PT1#2.7)
MTR_N: Z1-Sugarland (M1#1.4 PT1#1.8), Z1-Sugarland-Simplified (M1#2.4 PT1#2.8)
NAC_N: Z1-Sugarland (FACP1#1.13 R4#1.2 SIR1#1.2 STB1#1.2), Z1-Sugarland-Simplified (FACP1#2.13 R4#2.2 SIR1#2.2 STB1#2.2)
NAC_P: Z1-Sugarland (FACP1#1.12 R4#1.1 SIR1#1.1 STB1#1.1), Z1-Sugarland-Simplified (FACP1#2.12 R4#2.1 SIR1#2.1 STB1#2.1)
PSN_TRB_A: Z1-Sugarland (MM3#1.3 PSN1#1.18 R12#1.1), Z1-Sugarland-Simplified (MM3#2.3 PSN1#2.18 R12#2.1)
PSN_TRB_B: Z1-Sugarland (MM3#1.4 PSN1#1.19 R12#1.2), Z1-Sugarland-Simplified (MM3#2.4 PSN1#2.19 R12#2.2)
PSNBAT_MID: Z1-Sugarland (BAT3#1.2 BAT4#1.1), Z1-Sugarland-Simplified (BAT3#2.2 BAT4#2.1)
PSNBAT_N: Z1-Sugarland (BAT4#1.2 PSN1#1.5), Z1-Sugarland-Simplified (BAT4#2.2 PSN1#2.5)
PSNBAT_P: Z1-Sugarland (BAT3#1.1 PSN1#1.4), Z1-Sugarland-Simplified (BAT3#2.1 PSN1#2.4)
PSU1_L: Z1-Sugarland (F6#1.2 PSU1#1.1), Z1-Sugarland-Simplified (F6#2.2 PSU1#2.1)
PSU2_L: Z1-Sugarland (F7#1.2 PSU2#1.1), Z1-Sugarland-Simplified (F7#2.2 PSU2#2.1)
PSU3_L: Z1-Sugarland (F9#1.2 PSU3#1.1), Z1-Sugarland-Simplified (F9#2.2 PSU3#2.1)
PSU4_L: Z1-Sugarland (F19#1.2 PSU4#1.1), Z1-Sugarland-Simplified (F19#2.2 PSU4#2.1)
PSU_OK_A: Z1-Sugarland (IO1#1.7 RM1#1.5), Z1-Sugarland-Simplified (IO1#2.7 RM1#2.5)
PSU_OK_B: Z1-Sugarland (IO1#1.8 RM2#1.5), Z1-Sugarland-Simplified (IO1#2.8 RM2#2.5)
REL1_N: Z1-Sugarland (DS1#1.2 PSN1#1.13), Z1-Sugarland-Simplified (DS1#2.2 PSN1#2.13)
REL1_P: Z1-Sugarland (DS1#1.1 PSN1#1.12), Z1-Sugarland-Simplified (DS1#2.1 PSN1#2.12)
REL2_N: Z1-Sugarland (DS1#1.4 PSN1#1.15), Z1-Sugarland-Simplified (DS1#2.4 PSN1#2.15)
REL2_P: Z1-Sugarland (DS1#1.3 PSN1#1.14), Z1-Sugarland-Simplified (DS1#2.3 PSN1#2.14)
REL3_N: Z1-Sugarland (DS1#1.6 PSN1#1.17), Z1-Sugarland-Simplified (DS1#2.6 PSN1#2.17)
REL3_P: Z1-Sugarland (DS1#1.5 PSN1#1.16), Z1-Sugarland-Simplified (DS1#2.5 PSN1#2.16)
SEC_L1: Z1-Sugarland (CB2#1.1 CB9#1.1 T2#1.4), Z1-Sugarland-Simplified (CB2#2.1 CB9#2.1 T2#2.4)
SEC_L2: Z1-Sugarland (CB2#1.2 T2#1.6), Z1-Sugarland-Simplified (CB2#2.2 T2#2.6)
SEC_N: Z1-Sugarland (8 pins), Z1-Sugarland-Simplified (8 pins)
SLC_R3N: Z1-Sugarland (FACP1#1.11 TB9#1.2 X14#1.2), Z1-Sugarland-Simplified (FACP1#2.11 TB9#2.2 X14#2.2)
SLC_R3P: Z1-Sugarland (FACP1#1.10 TB9#1.1 X14#1.1), Z1-Sugarland-Simplified (FACP1#2.10 TB9#2.1 X14#2.1)
SLC_S1N: Z1-Sugarland (6 pins), Z1-Sugarland-Simplified (6 pins)
SLC_S1P: Z1-Sugarland (6 pins), Z1-Sugarland-Simplified (6 pins)
SPD_L1: Z1-Sugarland (CB1#1.4 SPD1#1.1), Z1-Sugarland-Simplified (CB1#2.4 SPD1#2.1)
SPD_L2: Z1-Sugarland (CB1#1.5 SPD1#1.2), Z1-Sugarland-Simplified (CB1#2.5 SPD1#2.2)
SPD_L3: Z1-Sugarland (CB1#1.6 SPD1#1.3), Z1-Sugarland-Simplified (CB1#2.6 SPD1#2.3)
SUP1_N: Z1-Sugarland (DS1#1.10 R5#1.2 TB14#1.2 X12#1.4), Z1-Sugarland-Simplified (DS1#2.10 R5#2.2 TB14#2.2 X12#2.4)
SUP1_P: Z1-Sugarland (DS1#1.9 R5#1.1 TB14#1.1 X12#1.3), Z1-Sugarland-Simplified (DS1#2.9 R5#2.1 TB14#2.1 X12#2.3)
SUP2_N: Z1-Sugarland (DS1#1.12 R6#1.2 TB14#1.4 X13#1.2), Z1-Sugarland-Simplified (DS1#2.12 R6#2.2 TB14#2.4 X13#2.2)
SUP2_P: Z1-Sugarland (DS1#1.11 R6#1.1 TB14#1.3 X13#1.1), Z1-Sugarland-Simplified (DS1#2.11 R6#2.1 TB14#2.3 X13#2.1)
SUP3_N: Z1-Sugarland (DS1#1.14 R7#1.2 TB14#1.6 X14#1.4), Z1-Sugarland-Simplified (DS1#2.14 R7#2.2 TB14#2.6 X14#2.4)
SUP3_P: Z1-Sugarland (DS1#1.13 R7#1.1 TB14#1.5 X14#1.3), Z1-Sugarland-Simplified (DS1#2.13 R7#2.1 TB14#2.5 X14#2.3)
TAP_L1: Z1-Sugarland (F1#1.2 PT1#1.1), Z1-Sugarland-Simplified (F1#2.2 PT1#2.1)
TAP_L2: Z1-Sugarland (F2#1.2 PT1#1.2), Z1-Sugarland-Simplified (F2#2.2 PT1#2.2)
TAP_L3: Z1-Sugarland (F3#1.2 PT1#1.3), Z1-Sugarland-Simplified (F3#2.2 PT1#2.3)
TRIG1_N: Z1-Sugarland (FACP1#1.15 PSN1#1.7), Z1-Sugarland-Simplified (FACP1#2.15 PSN1#2.7)
TRIG1_P: Z1-Sugarland (FACP1#1.14 PSN1#1.6), Z1-Sugarland-Simplified (FACP1#2.14 PSN1#2.6)
TRIG2_N: Z1-Sugarland (FACP1#1.17 PSN1#1.9), Z1-Sugarland-Simplified (FACP1#2.17 PSN1#2.9)
TRIG2_P: Z1-Sugarland (FACP1#1.16 PSN1#1.8), Z1-Sugarland-Simplified (FACP1#2.16 PSN1#2.8)
TRIG3_N: Z1-Sugarland (FACP1#1.19 PSN1#1.11), Z1-Sugarland-Simplified (FACP1#2.19 PSN1#2.11)
TRIG3_P: Z1-Sugarland (FACP1#1.18 PSN1#1.10), Z1-Sugarland-Simplified (FACP1#2.18 PSN1#2.10)
UPS_BUF: Z1-Sugarland (IO1#1.9 UPS1#1.6), Z1-Sugarland-Simplified (IO1#2.9 UPS1#2.6)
